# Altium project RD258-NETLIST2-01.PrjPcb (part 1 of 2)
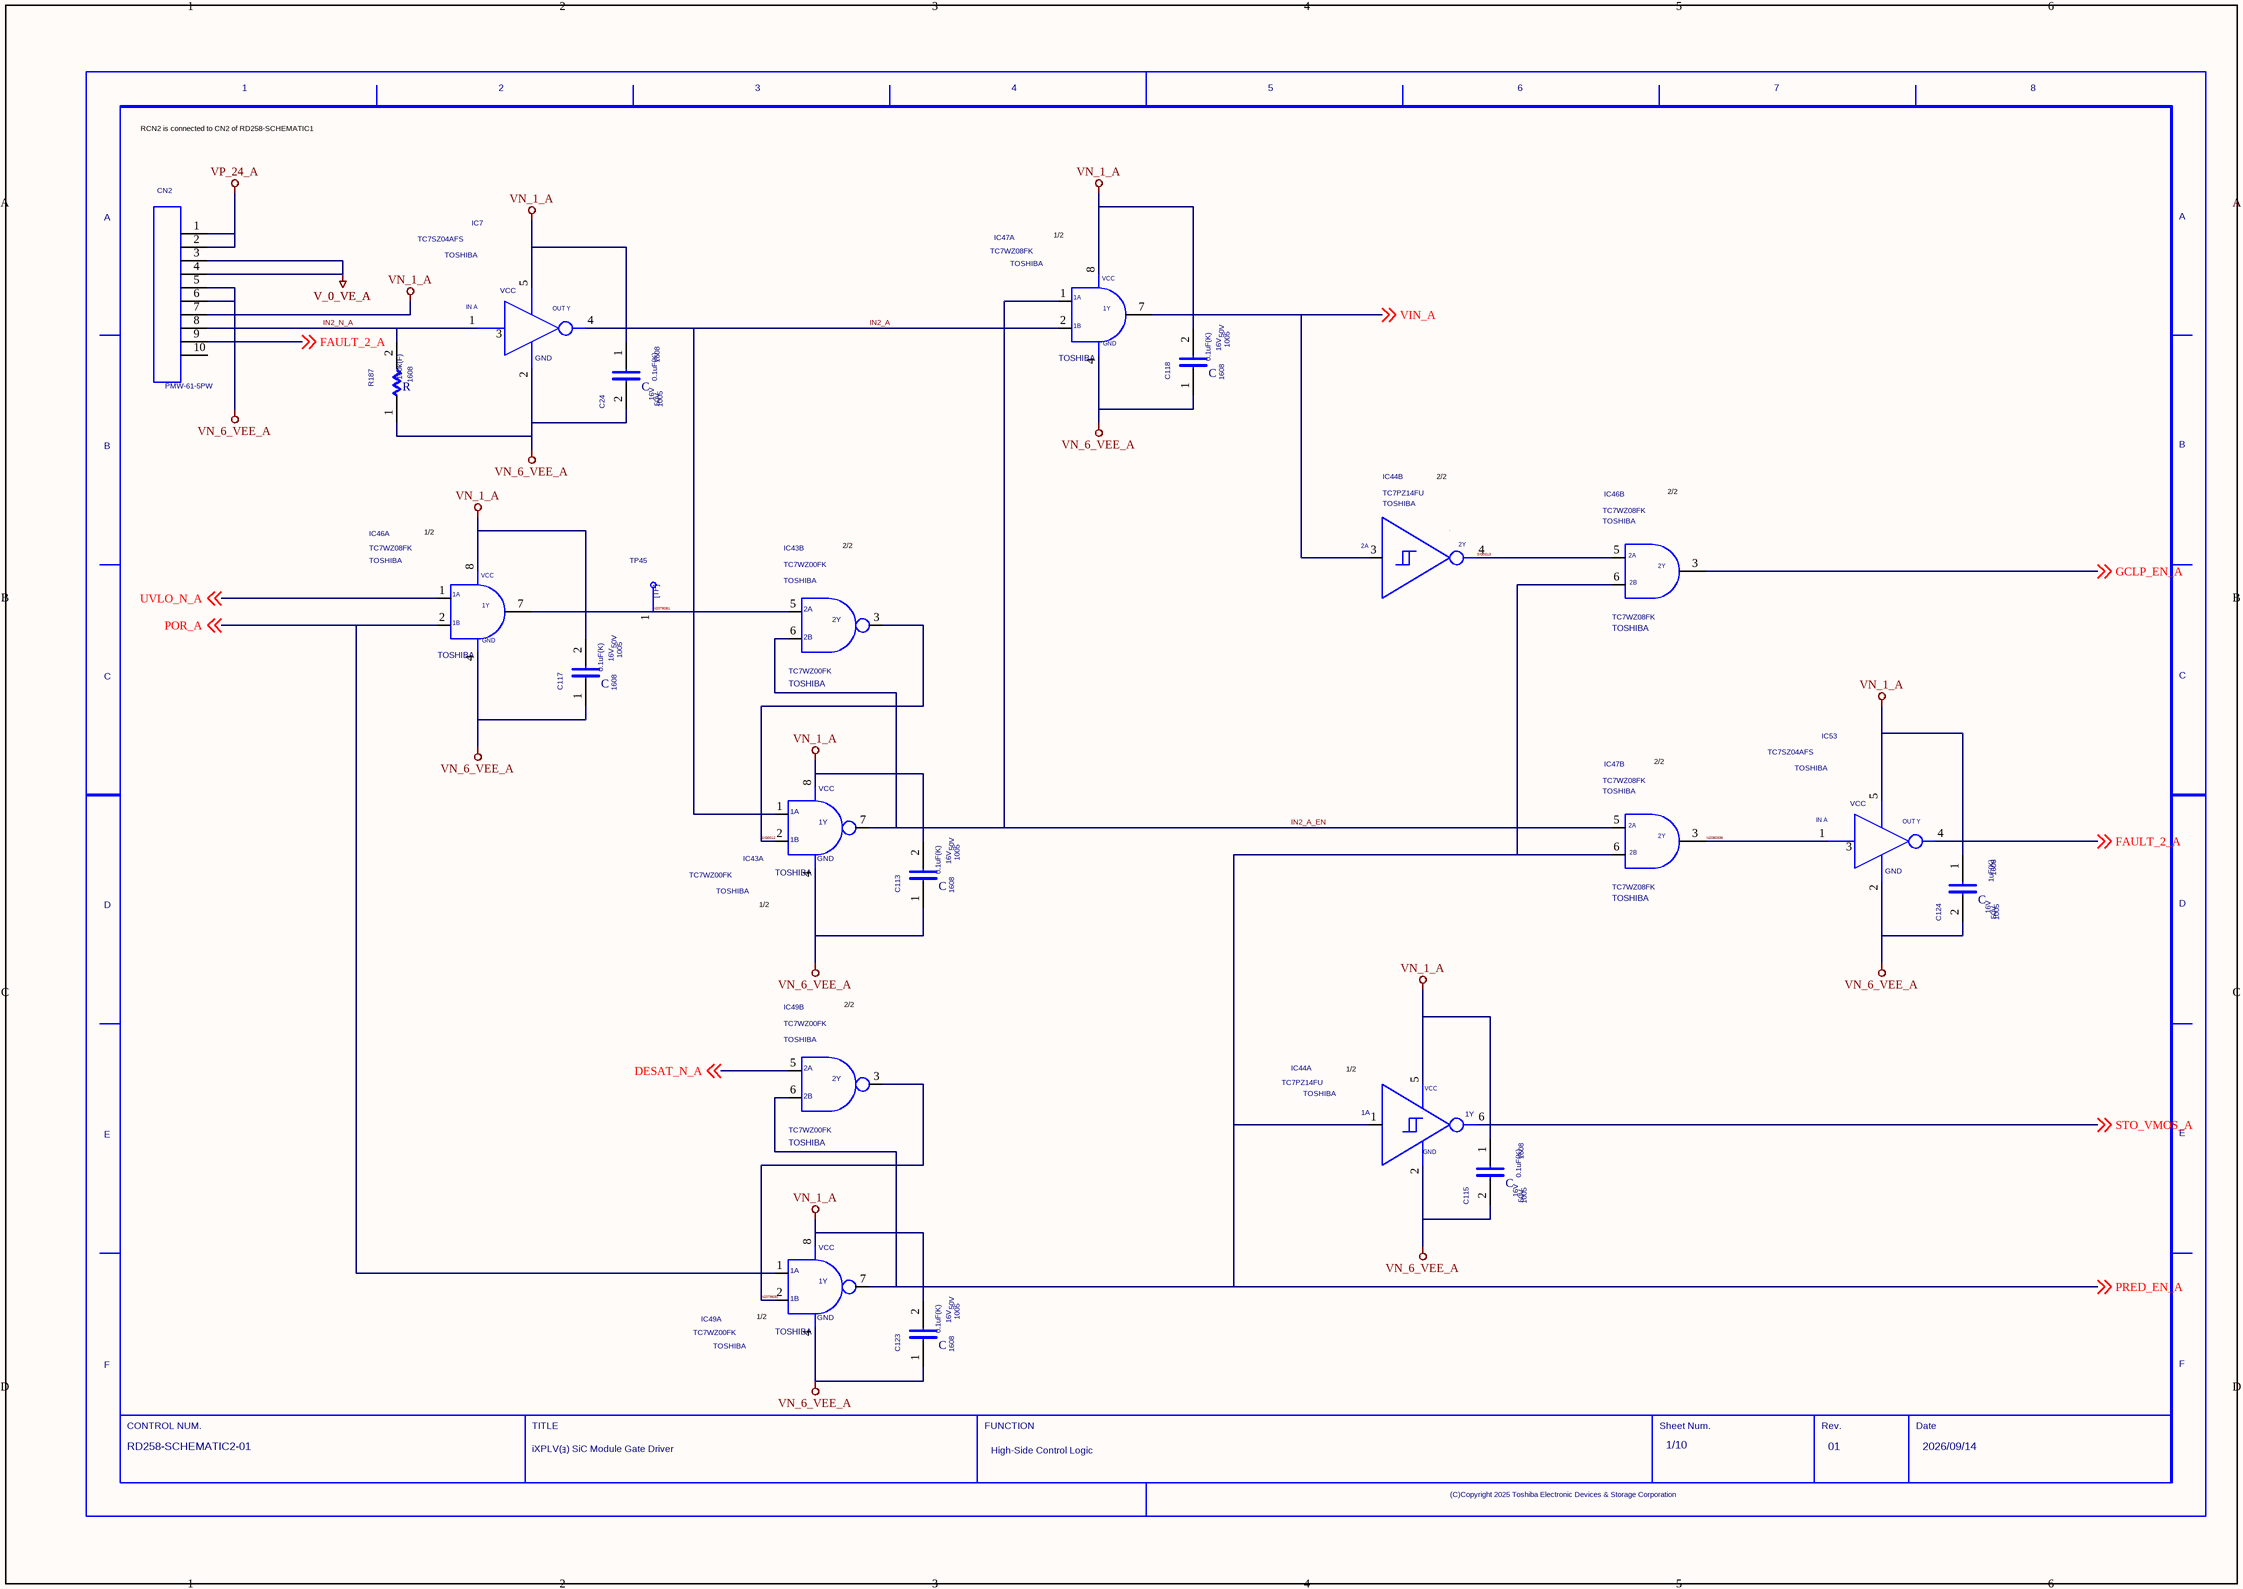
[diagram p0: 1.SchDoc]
10 sheets, 366 parts. Net scope: global (net labels, ports and power ports of the same name join across sheets).
Sheets:
  1.SchDoc
  2.SchDoc
  3.SchDoc
  4.SchDoc
  5.SchDoc
  6.SchDoc
  7.SchDoc
  8.SchDoc
  9.SchDoc
  10.SchDoc

## Sheet 1.SchDoc
size 420 x 297 mm

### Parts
(Parts that share a designator on the sheet are numbered #1, #2 ... from top to bottom, then left to right.)
C24  VAL1: 0.1uF(K)  CODE: 1005  VOLTAGE: 16V  SIZECODESMD: 1608  VAL2: 50V  (hidden comment: C)
C113  VAL1: 0.1uF(K)  CODE: 1005  VOLTAGE: 16V  SIZECODESMD: 1608  VAL2: 50V  (hidden comment: C)
C115  VAL1: 0.1uF(K)  CODE: 1005  VOLTAGE: 16V  SIZECODESMD: 1608  VAL2: 50V  (hidden comment: C)
C117  VAL1: 0.1uF(K)  CODE: 1005  VOLTAGE: 16V  SIZECODESMD: 1608  VAL2: 50V  (hidden comment: C)
C118  VAL1: 0.1uF(K)  CODE: 1005  VOLTAGE: 16V  SIZECODESMD: 1608  VAL2: 50V  (hidden comment: C)
C123  VAL1: 0.1uF(K)  CODE: 1005  VOLTAGE: 16V  SIZECODESMD: 1608  VAL2: 50V  (hidden comment: C)
C124  VAL1: 1uF(K)  CODE: 1005  VOLTAGE: 16V  SIZECODESMD: 1608  VAL2: 50V  (hidden comment: C)
CN2  VAL3: PMW-61-5PW  (hidden comment: CN9_2)
IC7  USERCOMPTEXT3: TOSHIBA  (hidden comment: TC7SZ04AFS)
IC43  VENDOR: TOSHIBA  (hidden comment: TC7WZ00FK)  (parts A,B of 2)
IC44  USERCOMPTEXT3: TOSHIBA  VAL3: TC7PZ14FU  (hidden comment: TC7PZ17FU)  (parts A,B of 2)
IC46  VENDOR: TOSHIBA  (hidden comment: TC7WZ08FK)  (parts A,B of 2)
IC47  VENDOR: TOSHIBA  (hidden comment: TC7WZ08FK)  (parts A,B of 2)
IC49  VENDOR: TOSHIBA  (hidden comment: TC7WZ00FK)  (parts A,B of 2)
IC53  USERCOMPTEXT3: TOSHIBA  (hidden comment: TC7SZ04AFS)
R187  VAL1: 100k(F)  SIZECODESMD: 1608  (hidden comment: R)
TP45  TP  (value not drawn)
U?#1  DATE: 2026/09/14  DRAWINGNUMBER: RD258-SCHEMATIC2-01  TITLE: iXPLV(ｮ) SiC Module Gate Driver  FUNCTION: High-Side Control Logic  SHEETNUMBER: 1/10  REVISION: 01  (hidden comment: WAKU_DEF100)

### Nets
V_0_VE_A: CN2.3 CN2.4
VN_1_A: C24.1 C113.2 C115.1 C117.2 C118.2 C123.2 C124.1 CN2.7 IC7.5 IC43.8 IC44.5 IC46.8 IC47.8 IC49.8 IC53.5
VN_6_VEE_A: C24.2 C113.1 C115.2 C117.1 C118.1 C123.1 C124.2 CN2.5 CN2.6 IC7.2 IC43.4 IC44.2 IC46.4 IC47.4 IC49.4 IC53.2 R187.1
VP_24_A: CN2.1 CN2.2
DESAT_N_A: IC49.5(2A) ; off-sheet DESAT_N_A
FAULT_2_A: CN2.9 IC53.4 ; off-sheet FAULT_2_A
GCLP_EN_A: IC46.3 ; off-sheet GCLP_EN_A
IN2_A: IC7.4 IC43.1 IC47.2
IN2_A_EN: IC43.6(2B) IC43.7 IC47.1 IC47.5
IN2_N_A: CN2.8 IC7.1 R187.2
N2078081: IC43.5(2A) IC46.7 TP45.1
N2078630: IC49.2 IC49.3(2Y)
N2080336: IC47.3 IC53.1
POR_A: IC46.2 IC49.1 ; off-sheet POR_A
PRED_EN_A: IC44.1 IC46.6 IC47.6 IC49.6(2B) IC49.7 ; off-sheet PRED_EN_A
SIG0012: IC43.2 IC43.3(2Y)
SIG0013: IC44.4 IC46.5
STO_VMOS_A: IC44.6 ; off-sheet STO_VMOS_A
UVLO_N_A: IC46.1 ; off-sheet UVLO_N_A
VIN_A: IC44.3 IC47.7 ; off-sheet VIN_A

Not connected (* = marked no-connect by the designer): CN2 10; IC7 3; IC53 3

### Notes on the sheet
- RCN2 is connected to CN2 of RD258-SCHEMATIC1
- (near IC47) 1/2
- (near IC46) 1/2
- 2/2
- (near IC43) 1/2
- (near IC44) 1/2
- (near IC49) 1/2

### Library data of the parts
C24 C113 C115 C117 C118 C123 C124 = C: TIME: 08:48:12; UPDATEUSER: HP_Z8_KEYSHOT; SAVECOUNT: 2; TC1: 0; PSPICETEMPLATE: C^@REFDES %1 %2 ?TOLERANCE¦C^@REFDES¦ @VALUE ?IC/IC=@IC/ TC=@TC1,@TC2 ?TOLERANCE¦\n.model C^@REFDES CAP C=1 DEV=@TOLERANCE% TC1=@TC1 TC2=@TC2 VC1=@VC1 VC2=@VC2¦; ORIGINALSYMBOLORIGIN: (0,0); INSTANCENAME: INS2265204
CN2 = CN10_1: TIME: 08:48:13; UPDATEUSER: t5459927; UPDATETIME: 15:38:59; SAVECOUNT: 3; PSPICETEMPLATE: X^@REFDES %1 %2 %3 %4 %5 %6 %7 %8 %9 %10 %M1 %M2 @MODEL; USER_VALUE: XG4A-1031; OriginalSymbolOrigin: (0,0)
IC7 IC53 = TC7SZ04AFS: TIME: 11:55:02; UPDATEUSER: t5459927; UPDATETIME: 19:30:29; SAVECOUNT: 6; PSPICETEMPLATE: X^@REFDES %INA %GND %NC %OUTY %VCC @MODEL; OriginalSymbolOrigin: (0,-5080); INSTANCENAME: INS2254048
IC43 IC49 = TC7WZ00FK_1: TIME: 08:52:39; UPDATEUSER: sptcae09; UPDATETIME: 16:09:46; SAVECOUNT: 9; SWAP_INFO: (S1+S2); ORDER: $pOrder; SPLIT_INST: TRUE; ・: 20mA; USER_VALUE: TC7W00FK; PSPICETEMPLATE: X^@REFDES %1A %1B %2Y %GND %2A %2B %1Y %VCC @MODEL; DESCRIPTION-A: NAND 2ch Logic; ORIGINALSYMBOLORIGIN: (2540,-2540); CaptureCellPackProp: TC7WZ00FK_1A; INSTANCENAME: INS2253652
IC44 = TC7PZ14FU_2: TIME: 11:55:01; UPDATEUSER: t5459927; UPDATETIME: 19:09:34; SAVECOUNT: 7; SPLIT_INST: TRUE; PSPICETEMPLATE: X^@REFDES %1A %GND %2A %2Y %VCC %1Y @MODEL; SWAP_INFO: (S1+S2); OriginalSymbolOrigin: (5080,15240); CaptureCellPackProp: TC7PZ14FU_2A; FUNCN: TC7PZ14FU_1; INSTANCENAME: INS2254016
IC46 IC47 = TC7WZ08FK_1: TIME: 08:52:39; UPDATEUSER: sptcae09; UPDATETIME: 16:09:46; SAVECOUNT: 5; SWAP_INFO: (S1+S2); ORDER: $pOrder; SPLIT_INST: TRUE; ・: 20mA; USER_VALUE: TC7W00FK; PSPICETEMPLATE: X^@REFDES %1A %1B %2Y %GND %2A %2B %1Y %VCC @MODEL; DESCRIPTION-A: NAND 2ch Logic; ORIGINALSYMBOLORIGIN: (2540,-2540); CaptureCellPackProp: TC7WZ08FK_1A; INSTANCENAME: INS2254084
R187 = R: TIME: 08:48:13; UPDATEUSER: HP_Z8_KEYSHOT; SAVECOUNT: 2; VAL2: 100mW; TC1: 0; PSPICETEMPLATE: R^@REFDES %1 %2 ?TOLERANCE¦R^@REFDES¦ @VALUE TC=@TC1,@TC2 ?TOLERANCE¦\n.model R^@REFDES RES R=1 DEV=@TOLERANCE% TC1=@TC1 TC2=@TC2¦; ORIGINALSYMBOLORIGIN: (0,0); INSTANCENAME: INS2263832
TP45 = TP: TIME: 16:12:21; UPDATEUSER: fukuda-y; UPDATETIME: 16:18:11; SAVECOUNT: 2; SAVEAREA0: -242,-92,12810,7836; ORIGINALSYMBOLORIGIN: (0,0); INSTANCENAME: INS2253720
U?#1 = WAKU_DEF100: PLOTTIME: HH:MM; SAVEAREA0: -63393,-16950,474261,314592; TIME: 14:30:25; UPDATEUSER: t5459927; UPDATETIME: 14:14:23; SAVECOUNT: 4; OriginalSymbolOrigin: (10160,284480); SHTSAVECOUNT: 37

## Sheet 2.SchDoc
size 420 x 297 mm
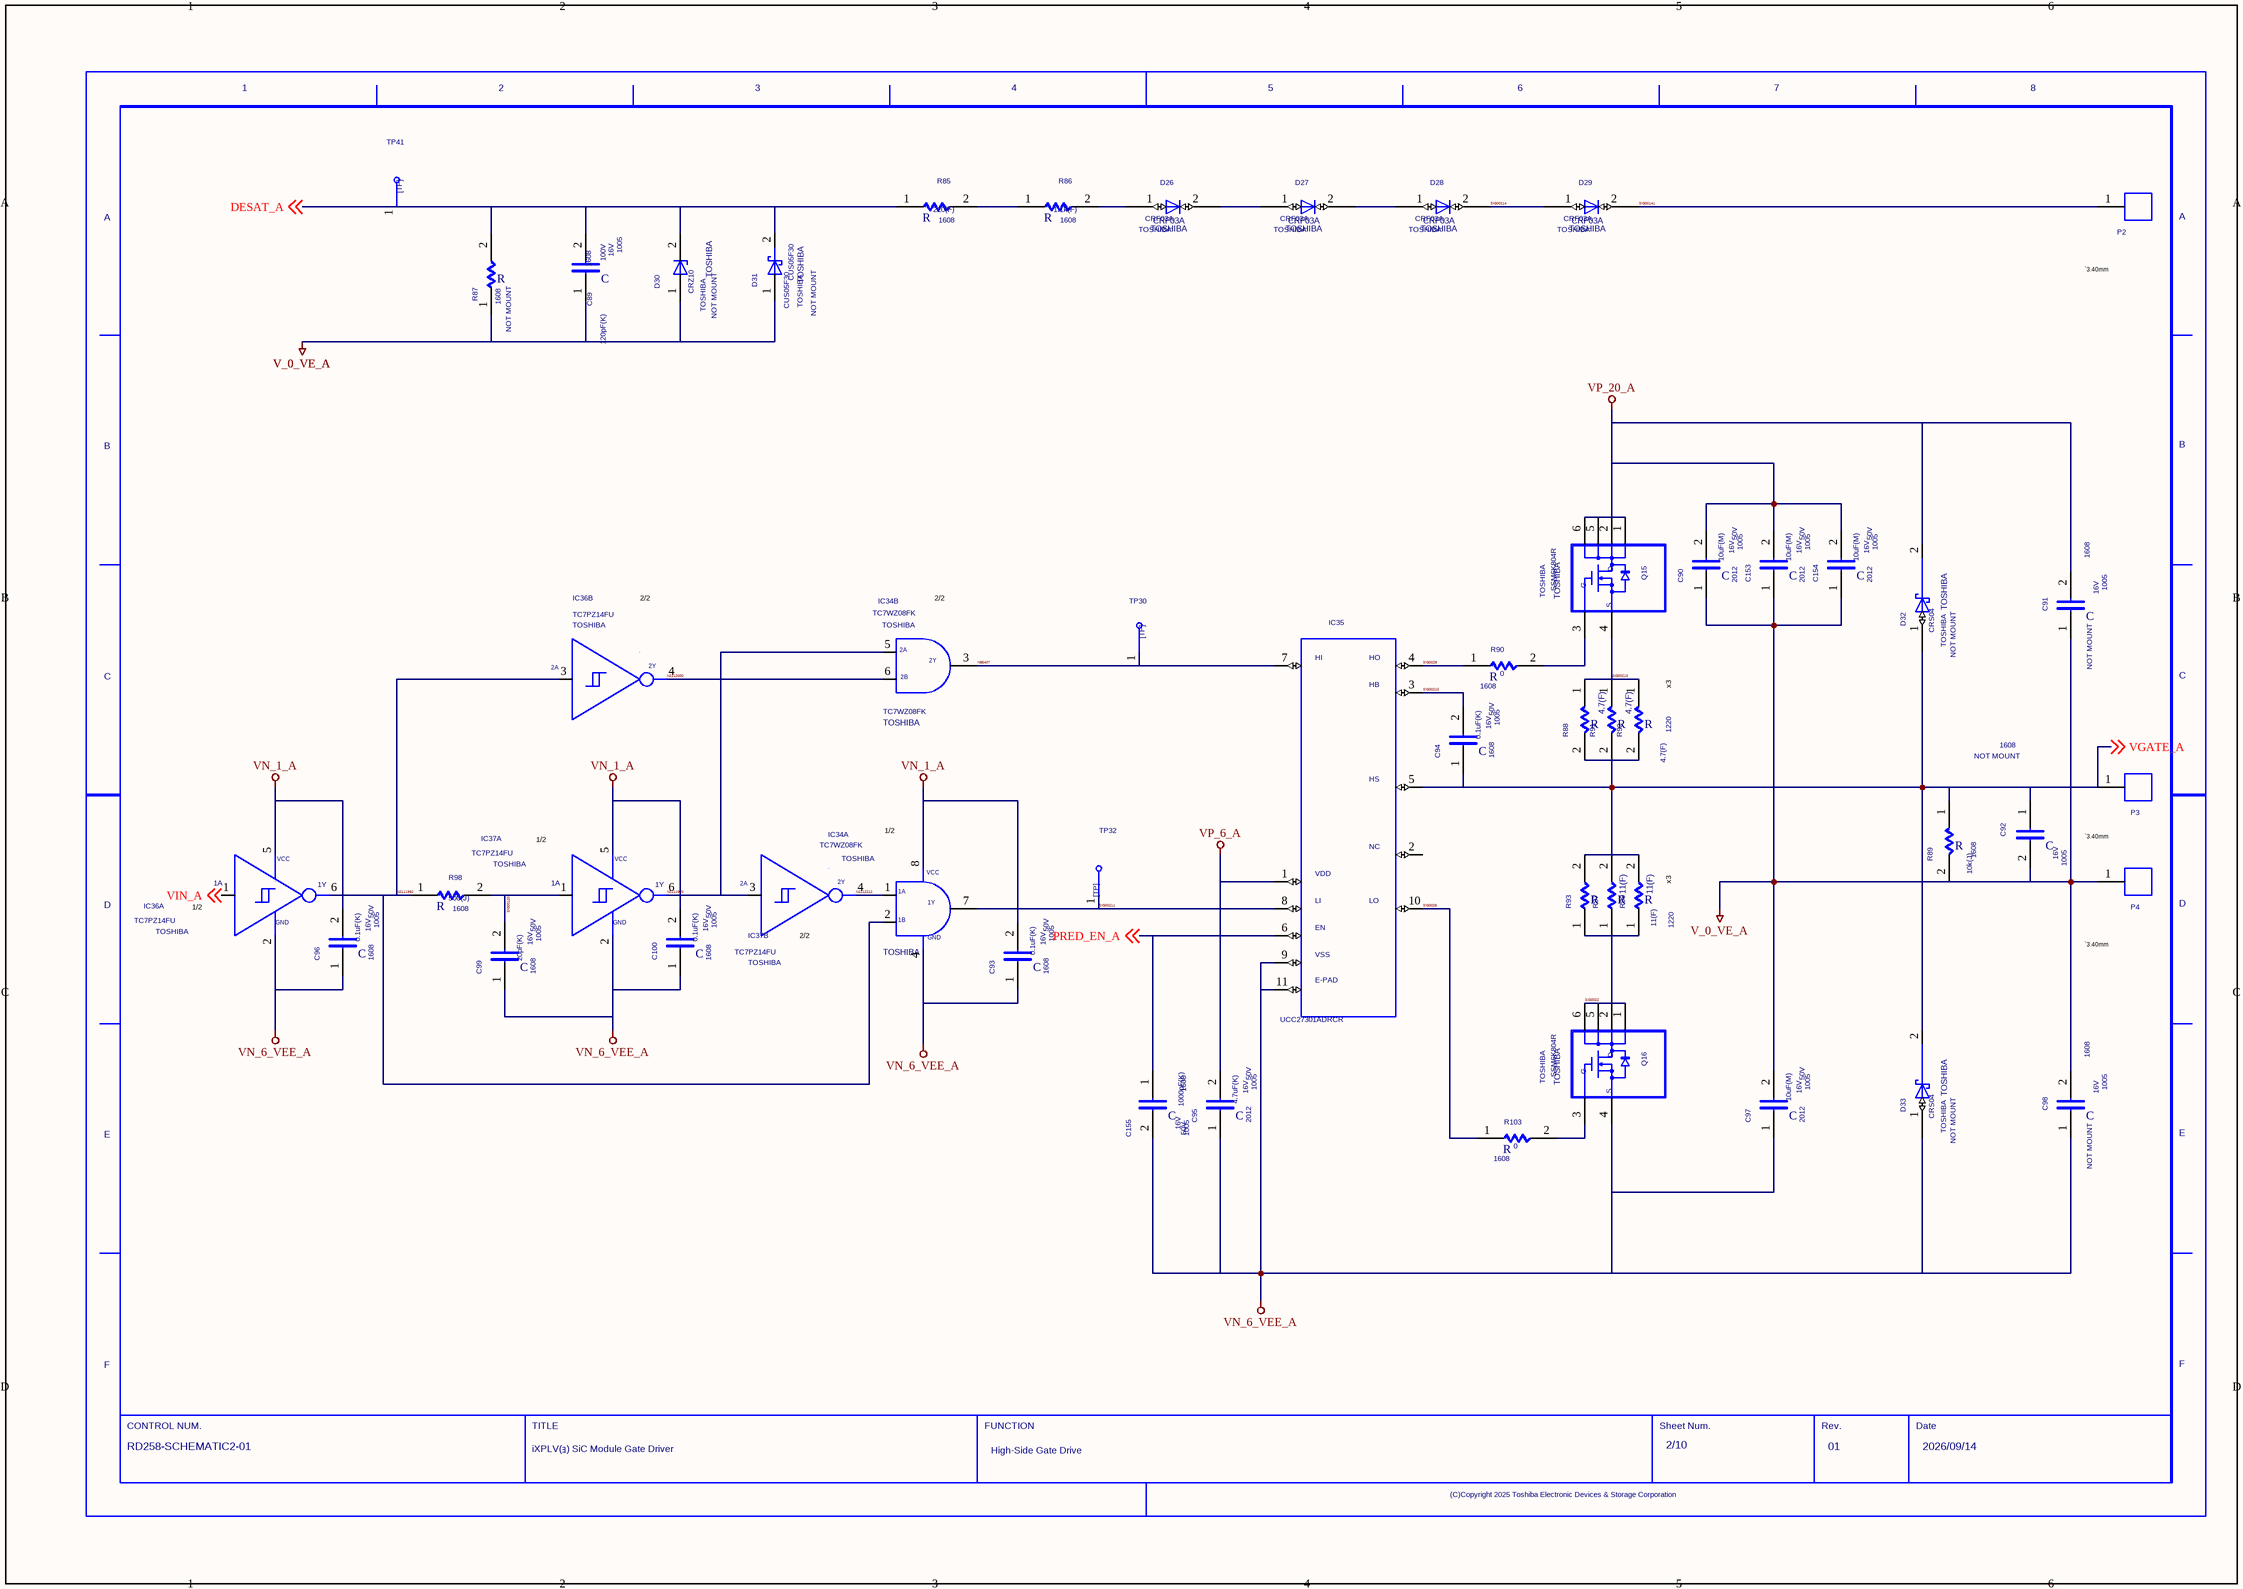
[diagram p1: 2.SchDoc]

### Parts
(Parts that share a designator on the sheet are numbered #1, #2 ... from top to bottom, then left to right.)
C89  VAL1: 120pF(K)  CODE: 1005  VOLTAGE: 16V  SIZECODESMD: 1608  VAL2: 100V  (hidden comment: C)
C90  VAL1: 10uF(M)  CODE: 1005  VOLTAGE: 16V  SIZECODESMD: 2012  VAL2: 50V  (hidden comment: C)
C91  CODE: 1005  VOLTAGE: 16V  NOTMOUNT: NOT MOUNT  SIZECODESMD: 1608  (hidden comment: C)
C92  CODE: 1005  VOLTAGE: 16V  NOTMOUNT: NOT MOUNT  SIZECODESMD: 1608  (hidden comment: C)
C93  VAL1: 0.1uF(K)  CODE: 1005  VOLTAGE: 16V  SIZECODESMD: 1608  VAL2: 50V  (hidden comment: C)
C94  VAL1: 0.1uF(K)  CODE: 1005  VOLTAGE: 16V  SIZECODESMD: 1608  VAL2: 50V  (hidden comment: C)
C95  VAL1: 4.7uF(K)  CODE: 1005  VOLTAGE: 16V  SIZECODESMD: 2012  VAL2: 50V  (hidden comment: C)
C96  VAL1: 0.1uF(K)  CODE: 1005  VOLTAGE: 16V  SIZECODESMD: 1608  VAL2: 50V  (hidden comment: C)
C97  VAL1: 10uF(M)  CODE: 1005  VOLTAGE: 16V  SIZECODESMD: 2012  VAL2: 50V  (hidden comment: C)
C98  CODE: 1005  VOLTAGE: 16V  NOTMOUNT: NOT MOUNT  SIZECODESMD: 1608  (hidden comment: C)
C99  VAL1: 20pF(K)  CODE: 1005  VOLTAGE: 16V  SIZECODESMD: 1608  VAL2: 50V  (hidden comment: C)
C100  VAL1: 0.1uF(K)  CODE: 1005  VOLTAGE: 16V  SIZECODESMD: 1608  VAL2: 50V  (hidden comment: C)
C153  VAL1: 10uF(M)  CODE: 1005  VOLTAGE: 16V  SIZECODESMD: 2012  VAL2: 50V  (hidden comment: C)
C154  VAL1: 10uF(M)  CODE: 1005  VOLTAGE: 16V  SIZECODESMD: 2012  VAL2: 50V  (hidden comment: C)
C155  VAL1: 1000pF(K)  CODE: 1005  VOLTAGE: 16V  SIZECODESMD: 1608  VAL2: 50V  (hidden comment: C)
D26  VENDOR: TOSHIBA  (hidden comment: CRF03A)
D27  VENDOR: TOSHIBA  (hidden comment: CRF03A)
D28  VENDOR: TOSHIBA  (hidden comment: CRF03A)
D29  VENDOR: TOSHIBA  (hidden comment: CRF03A)
D30  VENDOR: TOSHIBA  NOTMOUNT: NOT MOUNT  (hidden comment: CRZ10)
D31  VENDOR: TOSHIBA  NOTMOUNT: NOT MOUNT  (hidden comment: CUS05F30)
D32  VENDOR: TOSHIBA  NOTMOUNT: NOT MOUNT  (hidden comment: CRS04)
D33  VENDOR: TOSHIBA  NOTMOUNT: NOT MOUNT  (hidden comment: CRS04)
IC34  VENDOR: TOSHIBA  (hidden comment: TC7WZ08FK)  (parts A,B of 2)
IC35  VAL3: UCC27301ADRCR  (hidden comment: UCC27301A)
IC36  USERCOMPTEXT3: TOSHIBA  VAL3: TC7PZ14FU  (hidden comment: TC7PZ17FU)  (parts A,B of 2)
IC37  USERCOMPTEXT3: TOSHIBA  VAL3: TC7PZ14FU  (hidden comment: TC7PZ17FU)  (parts A,B of 2)
P2  TH  (value not drawn)
P3  TH  (value not drawn)
P4  TH  (value not drawn)
Q15  VENDOR: TOSHIBA  (hidden comment: SSM6K804R)
Q16  VENDOR: TOSHIBA  (hidden comment: SSM6K804R)
R85  VAL1: 220(F)  SIZECODESMD: 1608  (hidden comment: R)
R86  VAL1: 1.1k(F)  SIZECODESMD: 1608  (hidden comment: R)
R87  NOTMOUNT: NOT MOUNT  SIZECODESMD: 1608  (hidden comment: R)
R88  VAL1: 4.7(F)  SIZECODESMD: 1220  (hidden comment: R)
R89  VAL1: 10k(J)  SIZECODESMD: 1608  (hidden comment: R)
R90  VAL1: 0  SIZECODESMD: 1608  (hidden comment: R)
R91  VAL1: 4.7(F)  (hidden comment: R)
R92  VAL1: 4.7(F)  (hidden comment: R)
R93  VAL1: 11(F)  SIZECODESMD: 1220  (hidden comment: R)
R97  VAL1: 11(F)  (hidden comment: R)
R98  VAL1: 500(J)  SIZECODESMD: 1608  (hidden comment: R)
R99  VAL1: 11(F)  (hidden comment: R)
R103  VAL1: 0  SIZECODESMD: 1608  (hidden comment: R)
TP30  TP  (value not drawn)
TP32  TP  (value not drawn)
TP41  TP  (value not drawn)
U?#2  DATE: 2026/09/14  DRAWINGNUMBER: RD258-SCHEMATIC2-01  TITLE: iXPLV(ｮ) SiC Module Gate Driver  FUNCTION: High-Side Gate Drive  SHEETNUMBER: 2/10  REVISION: 01  (hidden comment: WAKU_DEF100)

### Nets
V_0_VE_A: C89.1 C90.1 C91.1 C92.2 C97.2 C98.2 C153.1 C154.1 D30.1(A) D31.1(A) P4.1 R87.1 R89.2
VN_1_A: C93.2 C96.2 C100.2 IC34.8 IC36.5 IC37.5
VN_6_VEE_A: C93.1 C95.1 C96.1 C97.1 C98.1 C99.1 C100.1 C155.2 D33.1(A) IC34.4 IC35.9 IC35.11 IC36.2 IC37.2 Q16.4
VP_6_A: C95.2 IC35.1
VP_20_A: C90.2 C91.2 C153.2 C154.2 D32.2(C) Q15.1 Q15.2 Q15.5 Q15.6
DESAT_A: C89.2 D30.2(C) D31.2(C) R85.1 R87.2 TP41.1 ; off-sheet DESAT_A
N85407: IC34.3 IC35.7 TP30.1
N2111970: IC34.5 IC37.3 IC37.6
N2111992: IC34.2 IC36.3 IC36.6 R98.1
N2112000: IC34.6 IC36.4
N2112212: IC34.1 IC37.4
PRED_EN_A: C155.1 IC35.6 ; off-sheet PRED_EN_A
SIG0022: Q16.1 Q16.2 Q16.5 Q16.6 R93.1 R97.1 R99.1
SIG0026: IC35.10 R103.1
SIG0028: IC35.4 R90.1
SIG00120: C99.2 IC37.1 R98.2
SIG00130: Q16.3 R103.2
SIG00136: Q15.3 R90.2
SIG00137: R85.2 R86.1
SIG00138: D26.1(A) R86.2
SIG00139: D26.2(C) D27.1(A)
SIG00140: D27.2(C) D28.1(A)
SIG00141: D29.2(C) P2.1
SIG00210: C94.2 IC35.3
SIG00211: IC34.7 IC35.8 TP32.1
SIG00213: Q15.4 R88.1 R91.1 R92.1
SIG00214: D28.2(C) D29.1(A)
VGATE_A: C92.1 C94.1 D32.1(A) D33.2(C) IC35.5 P3.1 R88.2 R89.1 R91.2 R92.2 R93.2 R97.2 R99.2 ; off-sheet VGATE_A
VIN_A: IC36.1 ; off-sheet VIN_A

Not connected (* = marked no-connect by the designer): IC35 2

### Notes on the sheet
- `3.40mm
  TH
- 2/2
- (near IC34) 2/2
- (near R92) x3
- (near IC37) 1/2
- (near IC34) 1/2
- (near IC36) 1/2
- (near IC37) 2/2
- (near R99) x3

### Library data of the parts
C89 C90 C93-C97 C99 C100 C153-C155 = C: as C24 on sheet 1
C91 C92 C98 = C: TIME: 08:48:12; UPDATEUSER: HP_Z8_KEYSHOT; SAVECOUNT: 2; TC1: 0; PSPICETEMPLATE: C^@REFDES %1 %2 ?TOLERANCE¦C^@REFDES¦ @VALUE ?IC/IC=@IC/ TC=@TC1,@TC2 ?TOLERANCE¦\n.model C^@REFDES CAP C=1 DEV=@TOLERANCE% TC1=@TC1 TC2=@TC2 VC1=@VC1 VC2=@VC2¦; ORIGINALSYMBOLORIGIN: (0,0); INSTANCENAME: INS2266227
D26-D29 = CRF03A: TIME: 08:48:14; UPDATEUSER: HP_Z8_KEYSHOT; SAVECOUNT: 2; PSPICETEMPLATE: X^@REFDES %A %C @MODEL; OriginalSymbolOrigin: (0,0); INSTANCENAME: INS2254974
D30 = CRZ10: TIME: 14:49:55; UPDATEUSER: fukuda-y; UPDATETIME: 08:18:42; SAVECOUNT: 6; SAVEAREA0: -4630,-153,17114,13055; PSPICETEMPLATE: X^@REFDES %A %C @MODEL; ORIGINALSYMBOLORIGIN: (0,0); INSTANCENAME: INS2255026
D31 = CUS05F30: TIME: 14:49:55; UPDATEUSER: fukuda-y; UPDATETIME: 08:16:22; SAVECOUNT: 9; SAVEAREA0: -4630,-153,17114,13055; PSPICETEMPLATE: X^@REFDES %A %C @MODEL; ORIGINALSYMBOLORIGIN: (0,0); INSTANCENAME: INS2255944
D32 D33 = CRS04: TIME: 08:48:14; UPDATEUSER: HP_Z8_KEYSHOT; SAVECOUNT: 2; PSPICETEMPLATE: X^@REFDES %A %C @MODEL; OriginalSymbolOrigin: (0,0); INSTANCENAME: INS2256112
IC34 = TC7WZ08FK_1: TIME: 08:52:39; UPDATEUSER: sptcae09; UPDATETIME: 16:09:46; SAVECOUNT: 9; SWAP_INFO: (S1+S2); ORDER: $pOrder; SPLIT_INST: TRUE; ・: 20mA; USER_VALUE: TC7W00FK; PSPICETEMPLATE: X^@REFDES %1A %1B %2Y %GND %2A %2B %1Y %VCC @MODEL; DESCRIPTION-A: NAND 2ch Logic; ORIGINALSYMBOLORIGIN: (2540,-2540); CaptureCellPackProp: TC7WZ08FK_1A; INSTANCENAME: INS2255192
IC35 = UCC27301A: TIME: 08:48:14; UPDATEUSER: t5459927; UPDATETIME: 20:55:41; SAVECOUNT: 11; PSPICETEMPLATE: X^@REFDES %VDD %NC %HB %HO %HS %EN %HI %LI %VSS %LO %THERMAL_PAD @MODEL; OriginalSymbolOrigin: (5080,60960)
IC36 IC37 = TC7PZ14FU_2: as IC44 on sheet 1
P2 = TH: TIME: 18:11:32; UPDATEUSER: w20165dm; SAVECOUNT: 1; PSPICETEMPLATE: X^@REFDES %1 @MODEL; ORIGINALSYMBOLORIGIN: (0,0); INSTANCENAME: INS2255754
P3 = TH: TIME: 18:11:32; UPDATEUSER: w20165dm; SAVECOUNT: 1; PSPICETEMPLATE: X^@REFDES %1 @MODEL; ORIGINALSYMBOLORIGIN: (0,0); INSTANCENAME: INS2255180
P4 = TH: TIME: 18:11:32; UPDATEUSER: w20165dm; SAVECOUNT: 1; PSPICETEMPLATE: X^@REFDES %1 @MODEL; ORIGINALSYMBOLORIGIN: (0,0); INSTANCENAME: INS2256066
Q15 Q16 = SSM6K804R: TIME: 08:48:15; UPDATEUSER: HP_Z8_KEYSHOT; SAVECOUNT: 14; SAVEAREA0: -7120,-295,29516,23636; ORIGINALSYMBOLORIGIN: (0,0); PSPICETEMPLATE: X^@REFDES %1 %2 %3 %4 %5 %6 @MODEL; INSTANCENAME: INS2255292
R85 R86 R98 = R: as R187 on sheet 1
R87 = R: TIME: 08:48:13; UPDATEUSER: HP_Z8_KEYSHOT; SAVECOUNT: 2; VAL2: 0.125; TC1: 0; PSPICETEMPLATE: R^@REFDES %1 %2 ?TOLERANCE¦R^@REFDES¦ @VALUE TC=@TC1,@TC2 ?TOLERANCE¦\n.model R^@REFDES RES R=1 DEV=@TOLERANCE% TC1=@TC1 TC2=@TC2¦; ORIGINALSYMBOLORIGIN: (0,0); INSTANCENAME: INS2263832
R88 R93 = R: TIME: 08:48:13; UPDATEUSER: HP_Z8_KEYSHOT; SAVECOUNT: 2; VAL2: 1W; TC1: 0; PSPICETEMPLATE: R^@REFDES %1 %2 ?TOLERANCE¦R^@REFDES¦ @VALUE TC=@TC1,@TC2 ?TOLERANCE¦\n.model R^@REFDES RES R=1 DEV=@TOLERANCE% TC1=@TC1 TC2=@TC2¦; ORIGINALSYMBOLORIGIN: (0,0); INSTANCENAME: INS2256002
R89 = R: TIME: 08:48:13; UPDATEUSER: HP_Z8_KEYSHOT; SAVECOUNT: 2; VAL2: 100mW; TC1: 0; PSPICETEMPLATE: R^@REFDES %1 %2 ?TOLERANCE¦R^@REFDES¦ @VALUE TC=@TC1,@TC2 ?TOLERANCE¦\n.model R^@REFDES RES R=1 DEV=@TOLERANCE% TC1=@TC1 TC2=@TC2¦; ORIGINALSYMBOLORIGIN: (0,0); INSTANCENAME: INS2266059
R90 R103 = R: TIME: 08:48:13; UPDATEUSER: HP_Z8_KEYSHOT; SAVECOUNT: 2; VAL2: 0.125; PSPICETEMPLATE: R^@REFDES %1 %2 ?TOLERANCE¦R^@REFDES¦ @VALUE TC=@TC1,@TC2 ?TOLERANCE¦\n.model R^@REFDES RES R=1 DEV=@TOLERANCE% TC1=@TC1 TC2=@TC2¦; ORIGINALSYMBOLORIGIN: (0,0); INSTANCENAME: INS2256002
R91 R92 R97 R99 = R: TIME: 08:48:13; UPDATEUSER: HP_Z8_KEYSHOT; SAVECOUNT: 2; VAL2: 1W; TC1: 0; PSPICETEMPLATE: R^@REFDES %1 %2 ?TOLERANCE¦R^@REFDES¦ @VALUE TC=@TC1,@TC2 ?TOLERANCE¦\n.model R^@REFDES RES R=1 DEV=@TOLERANCE% TC1=@TC1 TC2=@TC2¦; ORIGINALSYMBOLORIGIN: (0,0); SIZECODESMD: 1220; INSTANCENAME: INS2256002
TP30 = TP: TIME: 16:12:21; UPDATEUSER: fukuda-y; UPDATETIME: 16:18:11; SAVECOUNT: 2; SAVEAREA0: -242,-92,12810,7836; ORIGINALSYMBOLORIGIN: (0,0); INSTANCENAME: INS2255892
TP32 = TP: TIME: 16:12:21; UPDATEUSER: fukuda-y; UPDATETIME: 16:18:11; SAVECOUNT: 2; SAVEAREA0: -242,-92,12810,7836; ORIGINALSYMBOLORIGIN: (0,0); INSTANCENAME: INS2255530
TP41 = TP: TIME: 16:12:21; UPDATEUSER: fukuda-y; UPDATETIME: 16:18:11; SAVECOUNT: 2; SAVEAREA0: -242,-92,12810,7836; ORIGINALSYMBOLORIGIN: (0,0); INSTANCENAME: INS2255794
U?#2 = WAKU_DEF100: PLOTTIME: HH:MM; SAVEAREA0: -63393,-16950,474261,314592; TIME: 14:30:25; UPDATEUSER: t5459927; UPDATETIME: 14:20:04; SAVECOUNT: 4; OriginalSymbolOrigin: (10160,284480); SHTSAVECOUNT: 41

## Sheet 3.SchDoc
size 420 x 297 mm
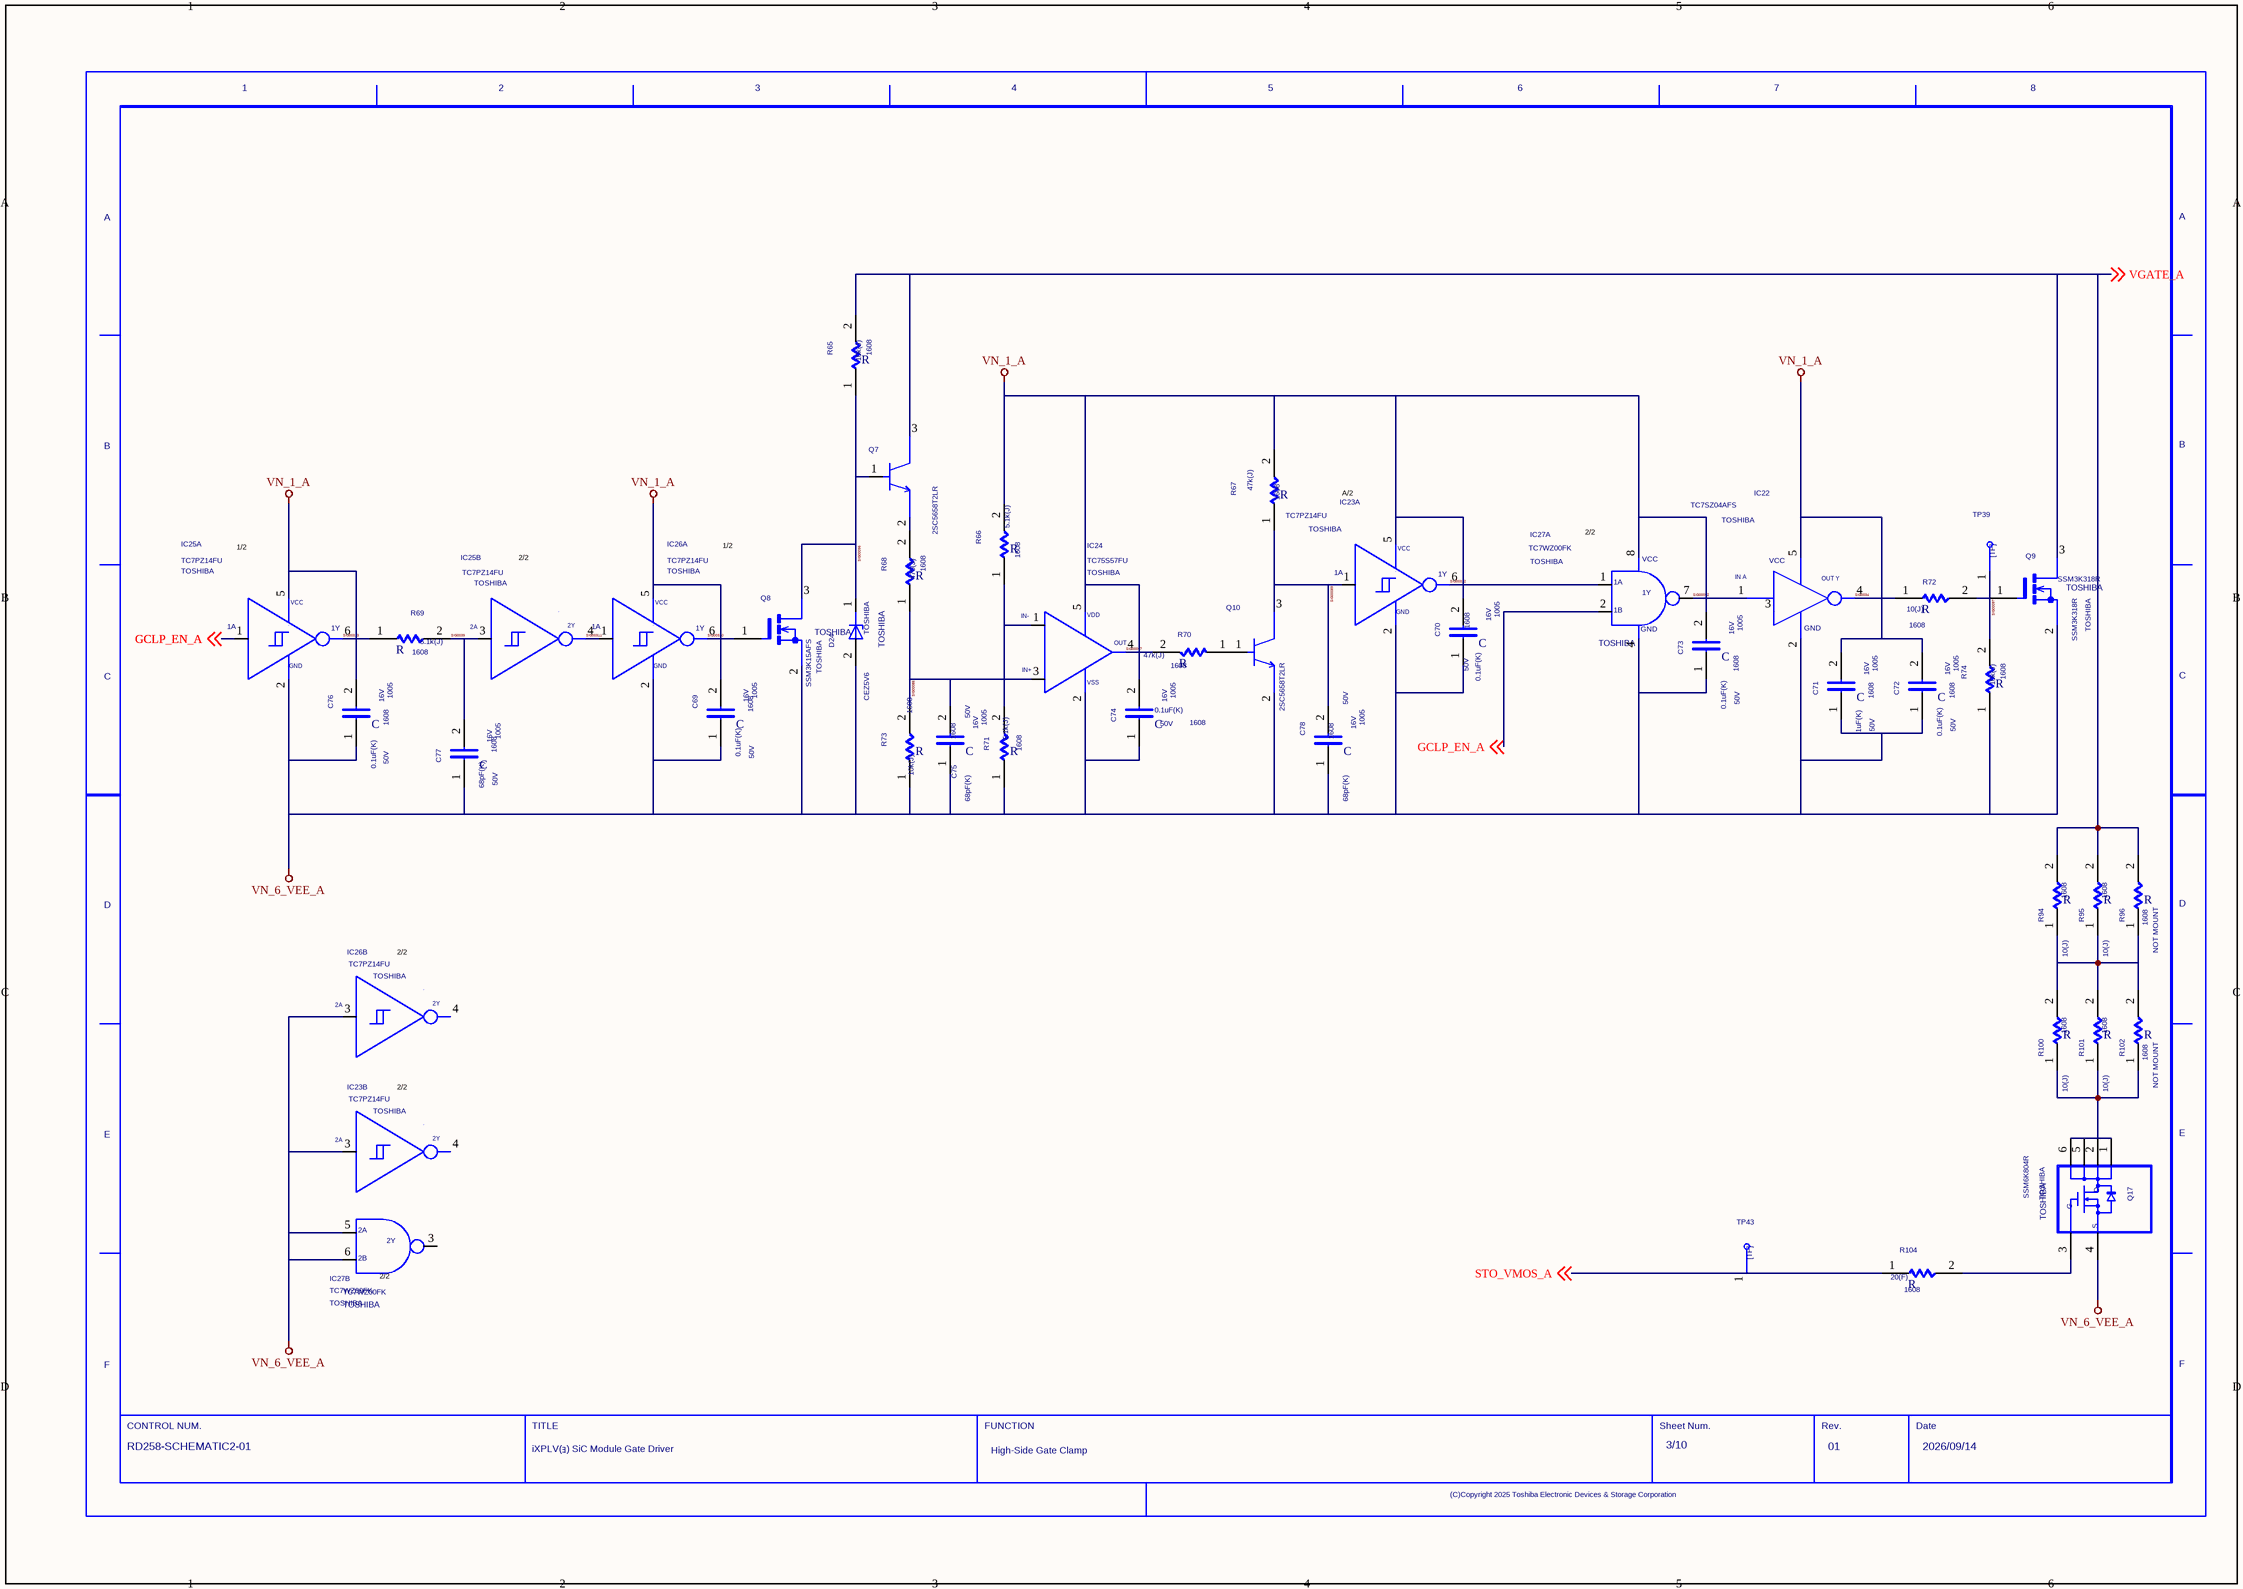
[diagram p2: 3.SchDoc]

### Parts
(Parts that share a designator on the sheet are numbered #1, #2 ... from top to bottom, then left to right.)
C69  VAL1: 0.1uF(K)  CODE: 1005  VOLTAGE: 16V  SIZECODESMD: 1608  VAL2: 50V  (hidden comment: C)
C70  VAL1: 0.1uF(K)  CODE: 1005  VOLTAGE: 16V  SIZECODESMD: 1608  VAL2: 50V  (hidden comment: C)
C71  VAL1: 1uF(K)  CODE: 1005  VOLTAGE: 16V  SIZECODESMD: 1608  VAL2: 50V  (hidden comment: C)
C72  VAL1: 0.1uF(K)  CODE: 1005  VOLTAGE: 16V  SIZECODESMD: 1608  VAL2: 50V  (hidden comment: C)
C73  VAL1: 0.1uF(K)  CODE: 1005  VOLTAGE: 16V  SIZECODESMD: 1608  VAL2: 50V  (hidden comment: C)
C74  VAL1: 0.1uF(K)  CODE: 1005  VOLTAGE: 16V  SIZECODESMD: 1608  VAL2: 50V  (hidden comment: C)
C75  VAL1: 68pF(K)  CODE: 1005  VOLTAGE: 16V  SIZECODESMD: 1608  VAL2: 50V  (hidden comment: C)
C76  VAL1: 0.1uF(K)  CODE: 1005  VOLTAGE: 16V  SIZECODESMD: 1608  VAL2: 50V  (hidden comment: C)
C77  VAL1: 68pF(K)  CODE: 1005  VOLTAGE: 16V  SIZECODESMD: 1608  VAL2: 50V  (hidden comment: C)
C78  VAL1: 68pF(K)  CODE: 1005  VOLTAGE: 16V  SIZECODESMD: 1608  VAL2: 50V  (hidden comment: C)
D24  VENDOR: TOSHIBA  (hidden comment: CEZ5V6)
IC22  USERCOMPTEXT3: TOSHIBA  (hidden comment: TC7SZ04AFS)
IC23  USERCOMPTEXT3: TOSHIBA  VAL3: TC7PZ14FU  (hidden comment: TC7PZ17FU)  (parts A,B of 2)
IC24  USERCOMPTEXT3: TOSHIBA  (hidden comment: TC75S57FU)
IC25  USERCOMPTEXT3: TOSHIBA  VAL3: TC7PZ14FU  (hidden comment: TC7PZ17FU)  (parts A,B of 2)
IC26  USERCOMPTEXT3: TOSHIBA  VAL3: TC7PZ14FU  (hidden comment: TC7PZ17FU)  (parts A,B of 2)
IC27  VENDOR: TOSHIBA  (hidden comment: TC7WZ00FK)  (parts A,B of 2)
Q7  VAL3: 2SC5658T2LR  (hidden comment: 2SC5658J)
Q8  VENDOR: TOSHIBA  (hidden comment: SSM3K15AFS)
Q9  VENDOR: TOSHIBA  (hidden comment: SSM3K318R)
Q10  VAL3: 2SC5658T2LR  (hidden comment: 2SC5658J)
Q17  VENDOR: TOSHIBA  (hidden comment: SSM6K804R)
R65  VAL1: 10k(J)  SIZECODESMD: 1608  (hidden comment: R)
R66  VAL1: 5.1k(J)  SIZECODESMD: 1608  (hidden comment: R)
R67  VAL1: 47k(J)  SIZECODESMD: 1608  (hidden comment: R)
R68  VAL1: 470(J)  SIZECODESMD: 1608  (hidden comment: R)
R69  VAL1: 5.1k(J)  SIZECODESMD: 1608  (hidden comment: R)
R70  VAL1: 47k(J)  SIZECODESMD: 1608  (hidden comment: R)
R71  VAL1: 5.1k(J)  SIZECODESMD: 1608  (hidden comment: R)
R72  VAL1: 10(J)  SIZECODESMD: 1608  (hidden comment: R)
R73  VAL1: 10k(J)  SIZECODESMD: 1608  (hidden comment: R)
R74  VAL1: 10k(J)  SIZECODESMD: 1608  (hidden comment: R)
R94  VAL1: 10(J)  SIZECODESMD: 1608  (hidden comment: R)
R95  VAL1: 10(J)  SIZECODESMD: 1608  (hidden comment: R)
R96  NOTMOUNT: NOT MOUNT  SIZECODESMD: 1608  (hidden comment: R)
R100  VAL1: 10(J)  SIZECODESMD: 1608  (hidden comment: R)
R101  VAL1: 10(J)  SIZECODESMD: 1608  (hidden comment: R)
R102  NOTMOUNT: NOT MOUNT  SIZECODESMD: 1608  (hidden comment: R)
R104  VAL1: 20(F)  SIZECODESMD: 1608  (hidden comment: R)
TP39  TP  (value not drawn)
TP43  TP  (value not drawn)
U?#3  DATE: 2026/09/14  DRAWINGNUMBER: RD258-SCHEMATIC2-01  TITLE: iXPLV(ｮ) SiC Module Gate Driver  FUNCTION: High-Side Gate Clamp  SHEETNUMBER: 3/10  REVISION: 01  (hidden comment: WAKU_DEF100)

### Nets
VN_1_A: C69.2 C70.2 C71.2 C72.2 C73.2 C74.2 C76.2 IC22.5 IC23.5 IC24.5 IC25.5 IC26.5 IC27.8 R66.2 R67.2
VN_6_VEE_A: C69.1 C70.1 C71.1 C72.1 C73.1 C74.1 C75.1 C76.1 C77.1 C78.1 D24.2(A) IC22.2 IC23.2 IC23.3 IC24.2 IC25.2 IC26.2 IC26.3 IC27.4 IC27.5(2A) IC27.6(2B) Q8.2(S) Q9.2(S) Q10.2(E) Q17.4 R71.1 R73.1 R74.1
GCLP_EN_A: IC25.1 IC27.2 ; off-sheet GCLP_EN_A
SIG0034: IC22.4 R72.1
SIG0039: C77.2 IC25.3 R69.2
SIG00085: C75.2 IC24.3 R68.1 R73.2
SIG00086: IC24.1 R66.1 R71.2
SIG00087: IC24.4 R70.2
SIG00089: C78.2 IC23.1 Q10.3(C) R67.1
SIG00092: IC22.1 IC27.7
SIG00096: D24.1(C) Q7.1(B) Q8.3(D) R65.1
SIG00097: Q9.1(G) R72.2 R74.2 TP39.1
SIG00098: Q7.2(E) R68.2
SIG00133: Q17.1 Q17.2 Q17.5 Q17.6 R100.1 R101.1 R102.1
SIG00134: Q17.3 R104.2
SIG00135: R94.1 R95.1 R96.1 R100.2 R101.2 R102.2
SIG00310: IC26.6 Q8.1(G)
SIG00311: IC25.4 IC26.1
SIG00312: IC23.6 IC27.1
SIG00313: IC25.6 R69.1
STO_VMOS_A: R104.1 TP43.1 ; off-sheet STO_VMOS_A
VGATE_A: Q7.3(C) Q9.3(D) R65.2 R94.2 R95.2 R96.2 ; off-sheet VGATE_A
NetQ10_1: Q10.1(B) R70.1

Not connected (* = marked no-connect by the designer): IC22 3; IC23 4; IC26 4; IC27 3(2Y)

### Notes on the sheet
- A/2
- (near IC27) 2/2
- (near IC25) 1/2
- 2/2
- 1/2

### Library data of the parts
C69-C78 = C: as C24 on sheet 1
D24 = CEZ5V6: TIME: 14:49:55; UPDATEUSER: fukuda-y; UPDATETIME: 08:16:22; SAVECOUNT: 9; SAVEAREA0: -4630,-153,17114,13055; PSPICETEMPLATE: X^@REFDES %C %A @MODEL; ORIGINALSYMBOLORIGIN: (0,0); INSTANCENAME: INS2262356
IC22 = TC7SZ04AFS: TIME: 11:55:02; UPDATEUSER: t5459927; UPDATETIME: 19:30:29; SAVECOUNT: 6; PSPICETEMPLATE: X^@REFDES %INA %GND %NC %OUTY %VCC @MODEL; OriginalSymbolOrigin: (0,-5080); INSTANCENAME: INS2262788
IC23 IC25 IC26 = TC7PZ14FU_2: TIME: 11:55:01; UPDATEUSER: t5459927; UPDATETIME: 19:09:34; SAVECOUNT: 7; SPLIT_INST: TRUE; PSPICETEMPLATE: X^@REFDES %1A %GND %2A %2Y %VCC %1Y @MODEL; SWAP_INFO: (S1+S2); OriginalSymbolOrigin: (5080,15240); CaptureCellPackProp: TC7PZ14FU_2A; FUNCN: TC7PZ14FU_1
IC24 = TC75S57FU: TIME: 08:48:15; UPDATEUSER: t5459927; UPDATETIME: 11:03:38; SAVECOUNT: 2; PSPICETEMPLATE: X^@REFDES %INN %VSS %INP %OUT %VDD @MODEL; OriginalSymbolOrigin: (2540,0); INSTANCENAME: INS2262824
IC27 = TC7WZ00FK_1: TIME: 08:52:39; UPDATEUSER: sptcae09; UPDATETIME: 16:09:46; SAVECOUNT: 9; SWAP_INFO: (S1+S2); ORDER: $pOrder; SPLIT_INST: TRUE; ・: 20mA; USER_VALUE: TC7W00FK; PSPICETEMPLATE: X^@REFDES %1A %1B %2Y %GND %2A %2B %1Y %VCC @MODEL; DESCRIPTION-A: NAND 2ch Logic; ORIGINALSYMBOLORIGIN: (2540,-2540); CaptureCellPackProp: TC7WZ00FK_1A
Q7 = 2SC5658J: TIME: 09:39:04; UPDATEUSER: 19910145; UPDATETIME: 15:12:10; SAVECOUNT: 8; VENDOR: ROHM; SAVEAREA0: -6194,-158,18648,15662; PSPICETEMPLATE: X^@REFDES %C %B %E @MODEL; ORIGINALSYMBOLORIGIN: (0,0); INSTANCENAME: INS2262598
Q8 = SSM3K15AFS: TIME: 08:48:15; UPDATEUSER: HP_Z8_KEYSHOT; SAVECOUNT: 2; ORIGINALSYMBOLORIGIN: (0,0); PSPICETEMPLATE: X^@REFDES %D %G %S @MODEL; INSTANCENAME: INS2262996
Q9 = SSM3K318R: TIME: 08:48:16; UPDATEUSER: HP_Z8_KEYSHOT; SAVECOUNT: 2; ORIGINALSYMBOLORIGIN: (0,0); PSPICETEMPLATE: X^@REFDES %D %G %S @MODEL; INSTANCENAME: INS2261964
Q10 = 2SC5658J: TIME: 09:39:04; UPDATEUSER: 19910145; UPDATETIME: 15:12:10; SAVECOUNT: 8; VENDOR: ROHM; SAVEAREA0: -6194,-158,18648,15662; PSPICETEMPLATE: X^@REFDES %C %B %E @MODEL; ORIGINALSYMBOLORIGIN: (0,0); INSTANCENAME: INS2262860
Q17 = SSM6K804R: TIME: 08:48:15; UPDATEUSER: HP_Z8_KEYSHOT; SAVECOUNT: 14; SAVEAREA0: -7120,-295,29516,23636; ORIGINALSYMBOLORIGIN: (0,0); PSPICETEMPLATE: X^@REFDES %1 %2 %3 %4 %5 %6 @MODEL; INSTANCENAME: INS2262956
R65-R71 R73 R74 R94 R95 R100 R101 R104 = R: as R187 on sheet 1
R72 = R: TIME: 08:48:13; UPDATEUSER: HP_Z8_KEYSHOT; SAVECOUNT: 2; VAL2: 100mW; TC1: 0; PSPICETEMPLATE: R^@REFDES %1 %2 ?TOLERANCE¦R^@REFDES¦ @VALUE TC=@TC1,@TC2 ?TOLERANCE¦\n.model R^@REFDES RES R=1 DEV=@TOLERANCE% TC1=@TC1 TC2=@TC2¦; ORIGINALSYMBOLORIGIN: (0,0); INSTANCENAME: INS2262084
R96 R102 = R: as R87 on sheet 2
TP39 = TP: TIME: 16:12:21; UPDATEUSER: fukuda-y; UPDATETIME: 16:18:11; SAVECOUNT: 2; SAVEAREA0: -242,-92,12810,7836; ORIGINALSYMBOLORIGIN: (0,0); INSTANCENAME: INS2262622
TP43 = TP: TIME: 16:12:21; UPDATEUSER: fukuda-y; UPDATETIME: 16:18:11; SAVECOUNT: 2; SAVEAREA0: -242,-92,12810,7836; ORIGINALSYMBOLORIGIN: (0,0); INSTANCENAME: INS2262916
U?#3 = WAKU_DEF100: PLOTTIME: HH:MM; SAVEAREA0: -63393,-16950,474261,314592; TIME: 14:30:25; UPDATEUSER: t5459927; UPDATETIME: 14:20:04; SAVECOUNT: 4; OriginalSymbolOrigin: (10160,284480); SHTSAVECOUNT: 29

## Sheet 4.SchDoc
size 420 x 297 mm
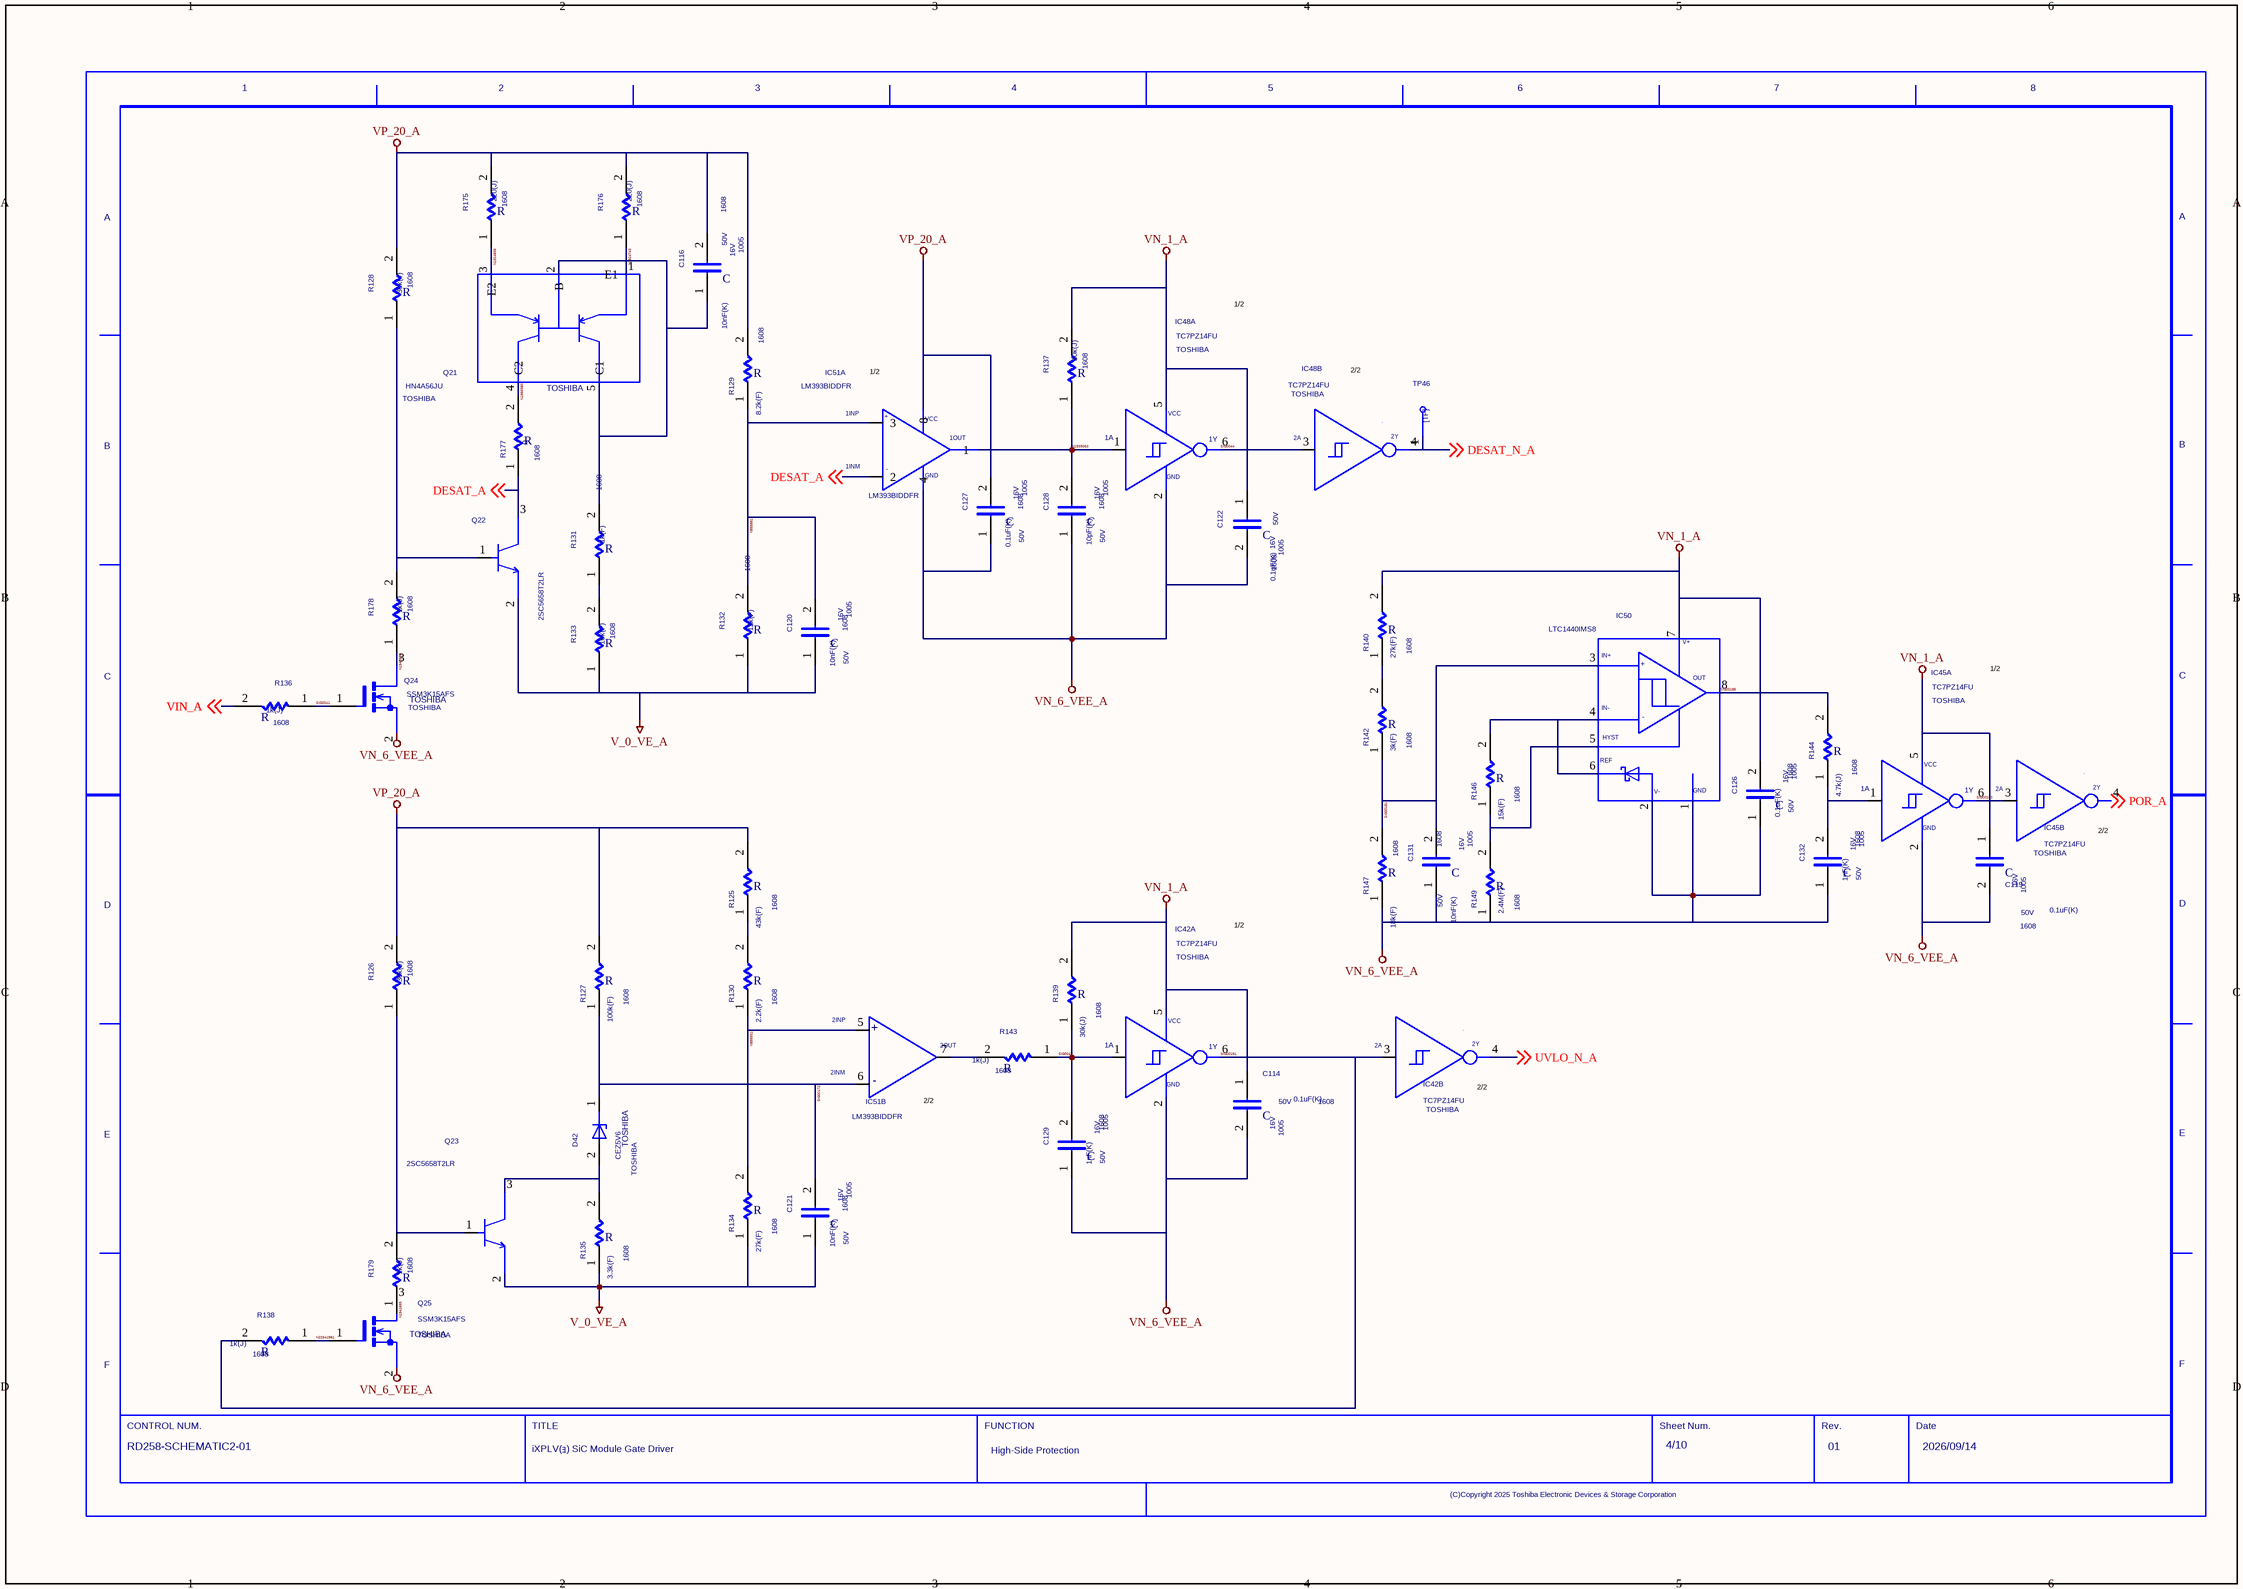
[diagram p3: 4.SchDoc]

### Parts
(Parts that share a designator on the sheet are numbered #1, #2 ... from top to bottom, then left to right.)
C114  VAL1: 0.1uF(K)  CODE: 1005  VOLTAGE: 16V  SIZECODESMD: 1608  VAL2: 50V  (hidden comment: C)
C116  VAL1: 10nF(K)  CODE: 1005  VOLTAGE: 16V  SIZECODESMD: 1608  VAL2: 50V  (hidden comment: C)
C119  VAL1: 0.1uF(K)  CODE: 1005  VOLTAGE: 16V  SIZECODESMD: 1608  VAL2: 50V  (hidden comment: C)
C120  VAL1: 10nF(K)  CODE: 1005  VOLTAGE: 16V  SIZECODESMD: 1608  VAL2: 50V  (hidden comment: C)
C121  VAL1: 10nF(K)  CODE: 1005  VOLTAGE: 16V  SIZECODESMD: 1608  VAL2: 50V  (hidden comment: C)
C122  VAL1: 0.1uF(K)  CODE: 1005  VOLTAGE: 16V  SIZECODESMD: 1608  VAL2: 50V  (hidden comment: C)
C126  VAL1: 0.1uF(K)  CODE: 1005  VOLTAGE: 16V  SIZECODESMD: 1608  VAL2: 50V  (hidden comment: C)
C127  VAL1: 0.1uF(K)  CODE: 1005  VOLTAGE: 16V  SIZECODESMD: 1608  VAL2: 50V  (hidden comment: C)
C128  VAL1: 10pF(K)  CODE: 1005  VOLTAGE: 16V  SIZECODESMD: 1608  VAL2: 50V  (hidden comment: C)
C129  VAL1: 1nF(K)  CODE: 1005  VOLTAGE: 16V  SIZECODESMD: 1608  VAL2: 50V  (hidden comment: C)
C131  VAL1: 10nF(K)  CODE: 1005  VOLTAGE: 16V  SIZECODESMD: 1608  VAL2: 50V  (hidden comment: C)
C132  VAL1: 1nF(K)  CODE: 1005  VOLTAGE: 16V  SIZECODESMD: 1608  VAL2: 50V  (hidden comment: C)
D42  VENDOR: TOSHIBA  (hidden comment: CEZ5V6)
IC42  USERCOMPTEXT3: TOSHIBA  VAL3: TC7PZ14FU  (hidden comment: TC7PZ17FU)  (parts A,B of 2)
IC45  USERCOMPTEXT3: TOSHIBA  VAL3: TC7PZ14FU  (hidden comment: TC7PZ17FU)  (parts A,B of 2)
IC48  USERCOMPTEXT3: TOSHIBA  VAL3: TC7PZ14FU  (hidden comment: TC7PZ17FU)  (parts A,B of 2)
IC50  VAL3: LTC1440IMS8  (hidden comment: LTC1440IS8)
IC51  VAL1: LM393BIDDFR  (hidden comment: LM393B_2)  (parts A,B of 2)
Q21  VENDOR: TOSHIBA  (hidden comment: HN4A56JU)
Q22  VAL3: 2SC5658T2LR  (hidden comment: 2SC5658J)
Q23  VAL3: 2SC5658T2LR  (hidden comment: 2SC5658J)
Q24  VENDOR: TOSHIBA  (hidden comment: SSM3K15AFS)
Q25  VENDOR: TOSHIBA  (hidden comment: SSM3K15AFS)
R125  VAL1: 43k(F)  SIZECODESMD: 1608  (hidden comment: R)
R126  VAL1: 30k(J)  SIZECODESMD: 1608  (hidden comment: R)
R127  VAL1: 100k(F)  SIZECODESMD: 1608  (hidden comment: R)
R128  VAL1: 30k(J)  SIZECODESMD: 1608  (hidden comment: R)
R129  VAL1: 8.2k(F)  SIZECODESMD: 1608  (hidden comment: R)
R130  VAL1: 2.2k(F)  SIZECODESMD: 1608  (hidden comment: R)
R131  VAL1: 1k(F)  SIZECODESMD: 1608  (hidden comment: R)
R132  VAL1: 12k(F)  SIZECODESMD: 1608  (hidden comment: R)
R133  VAL1: 10k(F)  SIZECODESMD: 1608  (hidden comment: R)
R134  VAL1: 27k(F)  SIZECODESMD: 1608  (hidden comment: R)
R135  VAL1: 3.3k(F)  SIZECODESMD: 1608  (hidden comment: R)
R136  VAL1: 1k(J)  SIZECODESMD: 1608  (hidden comment: R)
R137  VAL1: 30k(J)  SIZECODESMD: 1608  (hidden comment: R)
R138  VAL1: 1k(J)  SIZECODESMD: 1608  (hidden comment: R)
R139  VAL1: 30k(J)  SIZECODESMD: 1608  (hidden comment: R)
R140  VAL1: 27k(F)  SIZECODESMD: 1608  (hidden comment: R)
R142  VAL1: 3k(F)  SIZECODESMD: 1608  (hidden comment: R)
R143  VAL1: 1k(J)  SIZECODESMD: 1608  (hidden comment: R)
R144  VAL1: 4.7k(J)  SIZECODESMD: 1608  (hidden comment: R)
R146  VAL1: 15k(F)  SIZECODESMD: 1608  (hidden comment: R)
R147  VAL1: 18k(F)  SIZECODESMD: 1608  (hidden comment: R)
R149  VAL1: 2.4M(F)  SIZECODESMD: 1608  (hidden comment: R)
R175  VAL1: 220(J)  SIZECODESMD: 1608  (hidden comment: R)
R176  VAL1: 220(J)  SIZECODESMD: 1608  (hidden comment: R)
R177  VAL1: 0  SIZECODESMD: 1608  (hidden comment: R)
R178  VAL1: 1k(J)  SIZECODESMD: 1608  (hidden comment: R)
R179  VAL1: 1k(J)  SIZECODESMD: 1608  (hidden comment: R)
TP46  TP  (value not drawn)
U?#4  DATE: 2026/09/14  DRAWINGNUMBER: RD258-SCHEMATIC2-01  TITLE: iXPLV(ｮ) SiC Module Gate Driver  FUNCTION: High-Side Protection  SHEETNUMBER: 4/10  REVISION: 01  (hidden comment: WAKU_DEF100)

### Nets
V_0_VE_A: C120.1 C121.1 Q22.2(E) Q23.2(E) R132.1 R133.1 R134.1 R135.1
VN_1_A: C114.1 C119.1 C122.1 C126.2 IC42.5 IC45.5 IC48.5 IC50.7(V+) R137.2 R139.2 R140.2
VN_6_VEE_A: C114.2 C119.2 C122.2 C126.1 C127.1 C128.1 C129.1 C131.1 C132.1 IC42.2 IC45.2 IC48.2 IC50.1(GND) IC50.2(V-) IC51.4 Q24.2(S) Q25.2(S) R147.1 R149.1
VP_20_A: C116.2 C127.2 IC51.8 R125.2 R126.2 R127.2 R128.2 R129.2 R175.2 R176.2
DESAT_A: IC51.2 Q22.3(C) R177.1 ; off-sheet DESAT_A
DESAT_N_A: IC48.4 TP46.1 ; off-sheet DESAT_N_A
N855881: C120.2 IC51.3 R129.1 R132.2
N855931: IC51.5 R130.1 R134.2
N1924743: Q21.1(E1) R176.1
N1924835: Q21.3(E2) R175.1
N1939063: C128.2 IC48.1 IC51.1 R137.1
N1941594: Q24.3(D) R178.1
N1941665: Q25.3(D) R179.1
N1966980: Q21.4(C2) R177.2
N22641981: Q25.1(G) R138.1
POR_A: IC45.4 ; off-sheet POR_A
SIG0041: Q24.1(G) R136.1
SIG0043: C129.2 IC42.1 R139.1 R143.1
SIG0044: IC48.3 IC48.6
SIG00166: Q22.1(B) R128.1 R178.2
SIG00167: C116.1 Q21.2(B) Q21.5(C1) R131.2
SIG00168: R131.1 R133.2
SIG00170: Q23.1(B) R126.1 R179.2
SIG00171: D42.2(A) Q23.3(C) R135.2
SIG00172: C121.2 D42.1(C) IC51.6 R127.1
SIG00173: R125.1 R130.2
SIG00178: IC51.7 R143.2
SIG00180: R140.1 R142.2
SIG00181: C131.2 IC50.3(IN+) R142.1 R147.2
SIG00182: IC50.4(IN-) IC50.6(REF) R146.2
SIG00183: IC50.5(HYST) R146.1 R149.2
SIG00185: IC50.8(OUT) R144.2
SIG00186: C132.2 IC45.1 R144.1
SIG00191: IC42.3 IC42.6 R138.2
SIG00193: IC45.3 IC45.6
UVLO_N_A: IC42.4 ; off-sheet UVLO_N_A
VIN_A: R136.2 ; off-sheet VIN_A

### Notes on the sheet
- 1/2
- (near IC51) 1/2
- 2/2
- (near IC45) 2/2
- (near IC51) 2/2
- (near IC42) 2/2

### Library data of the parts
C114 C116 C119-C122 C126-C129 C131 C132 = C: as C24 on sheet 1
D42 = CEZ5V6: TIME: 14:49:55; UPDATEUSER: fukuda-y; UPDATETIME: 08:16:22; SAVECOUNT: 9; SAVEAREA0: -4630,-153,17114,13055; PSPICETEMPLATE: X^@REFDES %C %A @MODEL; ORIGINALSYMBOLORIGIN: (0,0); INSTANCENAME: INS2265024
IC42 IC45 IC48 = TC7PZ14FU_2: as IC44 on sheet 1
IC50 = LTC1440IS8: TIME: 08:48:16; UPDATEUSER: t5459927; UPDATETIME: 17:22:21; SAVECOUNT: 4; PSPICETEMPLATE: X^@REFDES %GND %V- %IN+ %IN- %HYST %REF %V+ %OUT @MODEL; OriginalSymbolOrigin: (0,0); INSTANCENAME: INS2264292
IC51 = LM393B_2: TIME: 08:48:12; UPDATEUSER: t5459927; UPDATETIME: 19:15:42; SAVECOUNT: 5; SPLIT_INST: TRUE; PSPICETEMPLATE: X^@REFDES %INN %VSS %INP %OUT %VDD @MODEL; COMP: LM393B; VENDOR: TI; SWAP_INFO: (S1+S2); OriginalSymbolOrigin: (2540,0); CaptureCellPackProp: LM393B_2A; FUNCN: LM393B_1; INSTANCENAME: INS2264892
Q21 = HN4A56JU: TIME: 08:48:13; UPDATEUSER: HP_Z8_KEYSHOT; SAVECOUNT: 2; PSPICETEMPLATE: X^@REFDES %B1 %E %B2 %C2 %C1 @MODEL; OriginalSymbolOrigin: (0,0); INSTANCENAME: INS2265108
Q22 = 2SC5658J: TIME: 09:39:04; UPDATEUSER: 19910145; UPDATETIME: 15:12:10; SAVECOUNT: 8; VENDOR: ROHM; SAVEAREA0: -6194,-158,18648,15662; PSPICETEMPLATE: X^@REFDES %C %B %E @MODEL; ORIGINALSYMBOLORIGIN: (0,0); INSTANCENAME: INS2264212
Q23 = 2SC5658J: TIME: 09:39:04; UPDATEUSER: 19910145; UPDATETIME: 15:12:10; SAVECOUNT: 8; VENDOR: ROHM; SAVEAREA0: -6194,-158,18648,15662; PSPICETEMPLATE: X^@REFDES %C %B %E @MODEL; ORIGINALSYMBOLORIGIN: (0,0); INSTANCENAME: INS2264508
Q24 = SSM3K15AFS: TIME: 08:48:15; UPDATEUSER: HP_Z8_KEYSHOT; SAVECOUNT: 2; ORIGINALSYMBOLORIGIN: (0,0); PSPICETEMPLATE: X^@REFDES %D %G %S @MODEL; INSTANCENAME: INS2265300
Q25 = SSM3K15AFS: TIME: 08:48:15; UPDATEUSER: HP_Z8_KEYSHOT; SAVECOUNT: 2; ORIGINALSYMBOLORIGIN: (0,0); PSPICETEMPLATE: X^@REFDES %D %G %S @MODEL; INSTANCENAME: INS2264184
R125-R140 R142-R144 R146 R147 R149 R175 R176 R178 R179 = R: as R187 on sheet 1
R177 = R: TIME: 08:48:13; UPDATEUSER: HP_Z8_KEYSHOT; SAVECOUNT: 2; VAL2: 0.125; PSPICETEMPLATE: R^@REFDES %1 %2 ?TOLERANCE¦R^@REFDES¦ @VALUE TC=@TC1,@TC2 ?TOLERANCE¦\n.model R^@REFDES RES R=1 DEV=@TOLERANCE% TC1=@TC1 TC2=@TC2¦; ORIGINALSYMBOLORIGIN: (0,0); INSTANCENAME: INS2264424
TP46 = TP: TIME: 16:12:21; UPDATEUSER: fukuda-y; UPDATETIME: 16:18:11; SAVECOUNT: 2; SAVEAREA0: -242,-92,12810,7836; ORIGINALSYMBOLORIGIN: (0,0); INSTANCENAME: INS2264820
U?#4 = WAKU_DEF100: PLOTTIME: HH:MM; SAVEAREA0: -63393,-16950,474261,314592; TIME: 14:30:25; UPDATEUSER: t5459927; UPDATETIME: 14:21:06; SAVECOUNT: 4; OriginalSymbolOrigin: (10160,284480); SHTSAVECOUNT: 36

## Sheet 5.SchDoc
size 420 x 297 mm
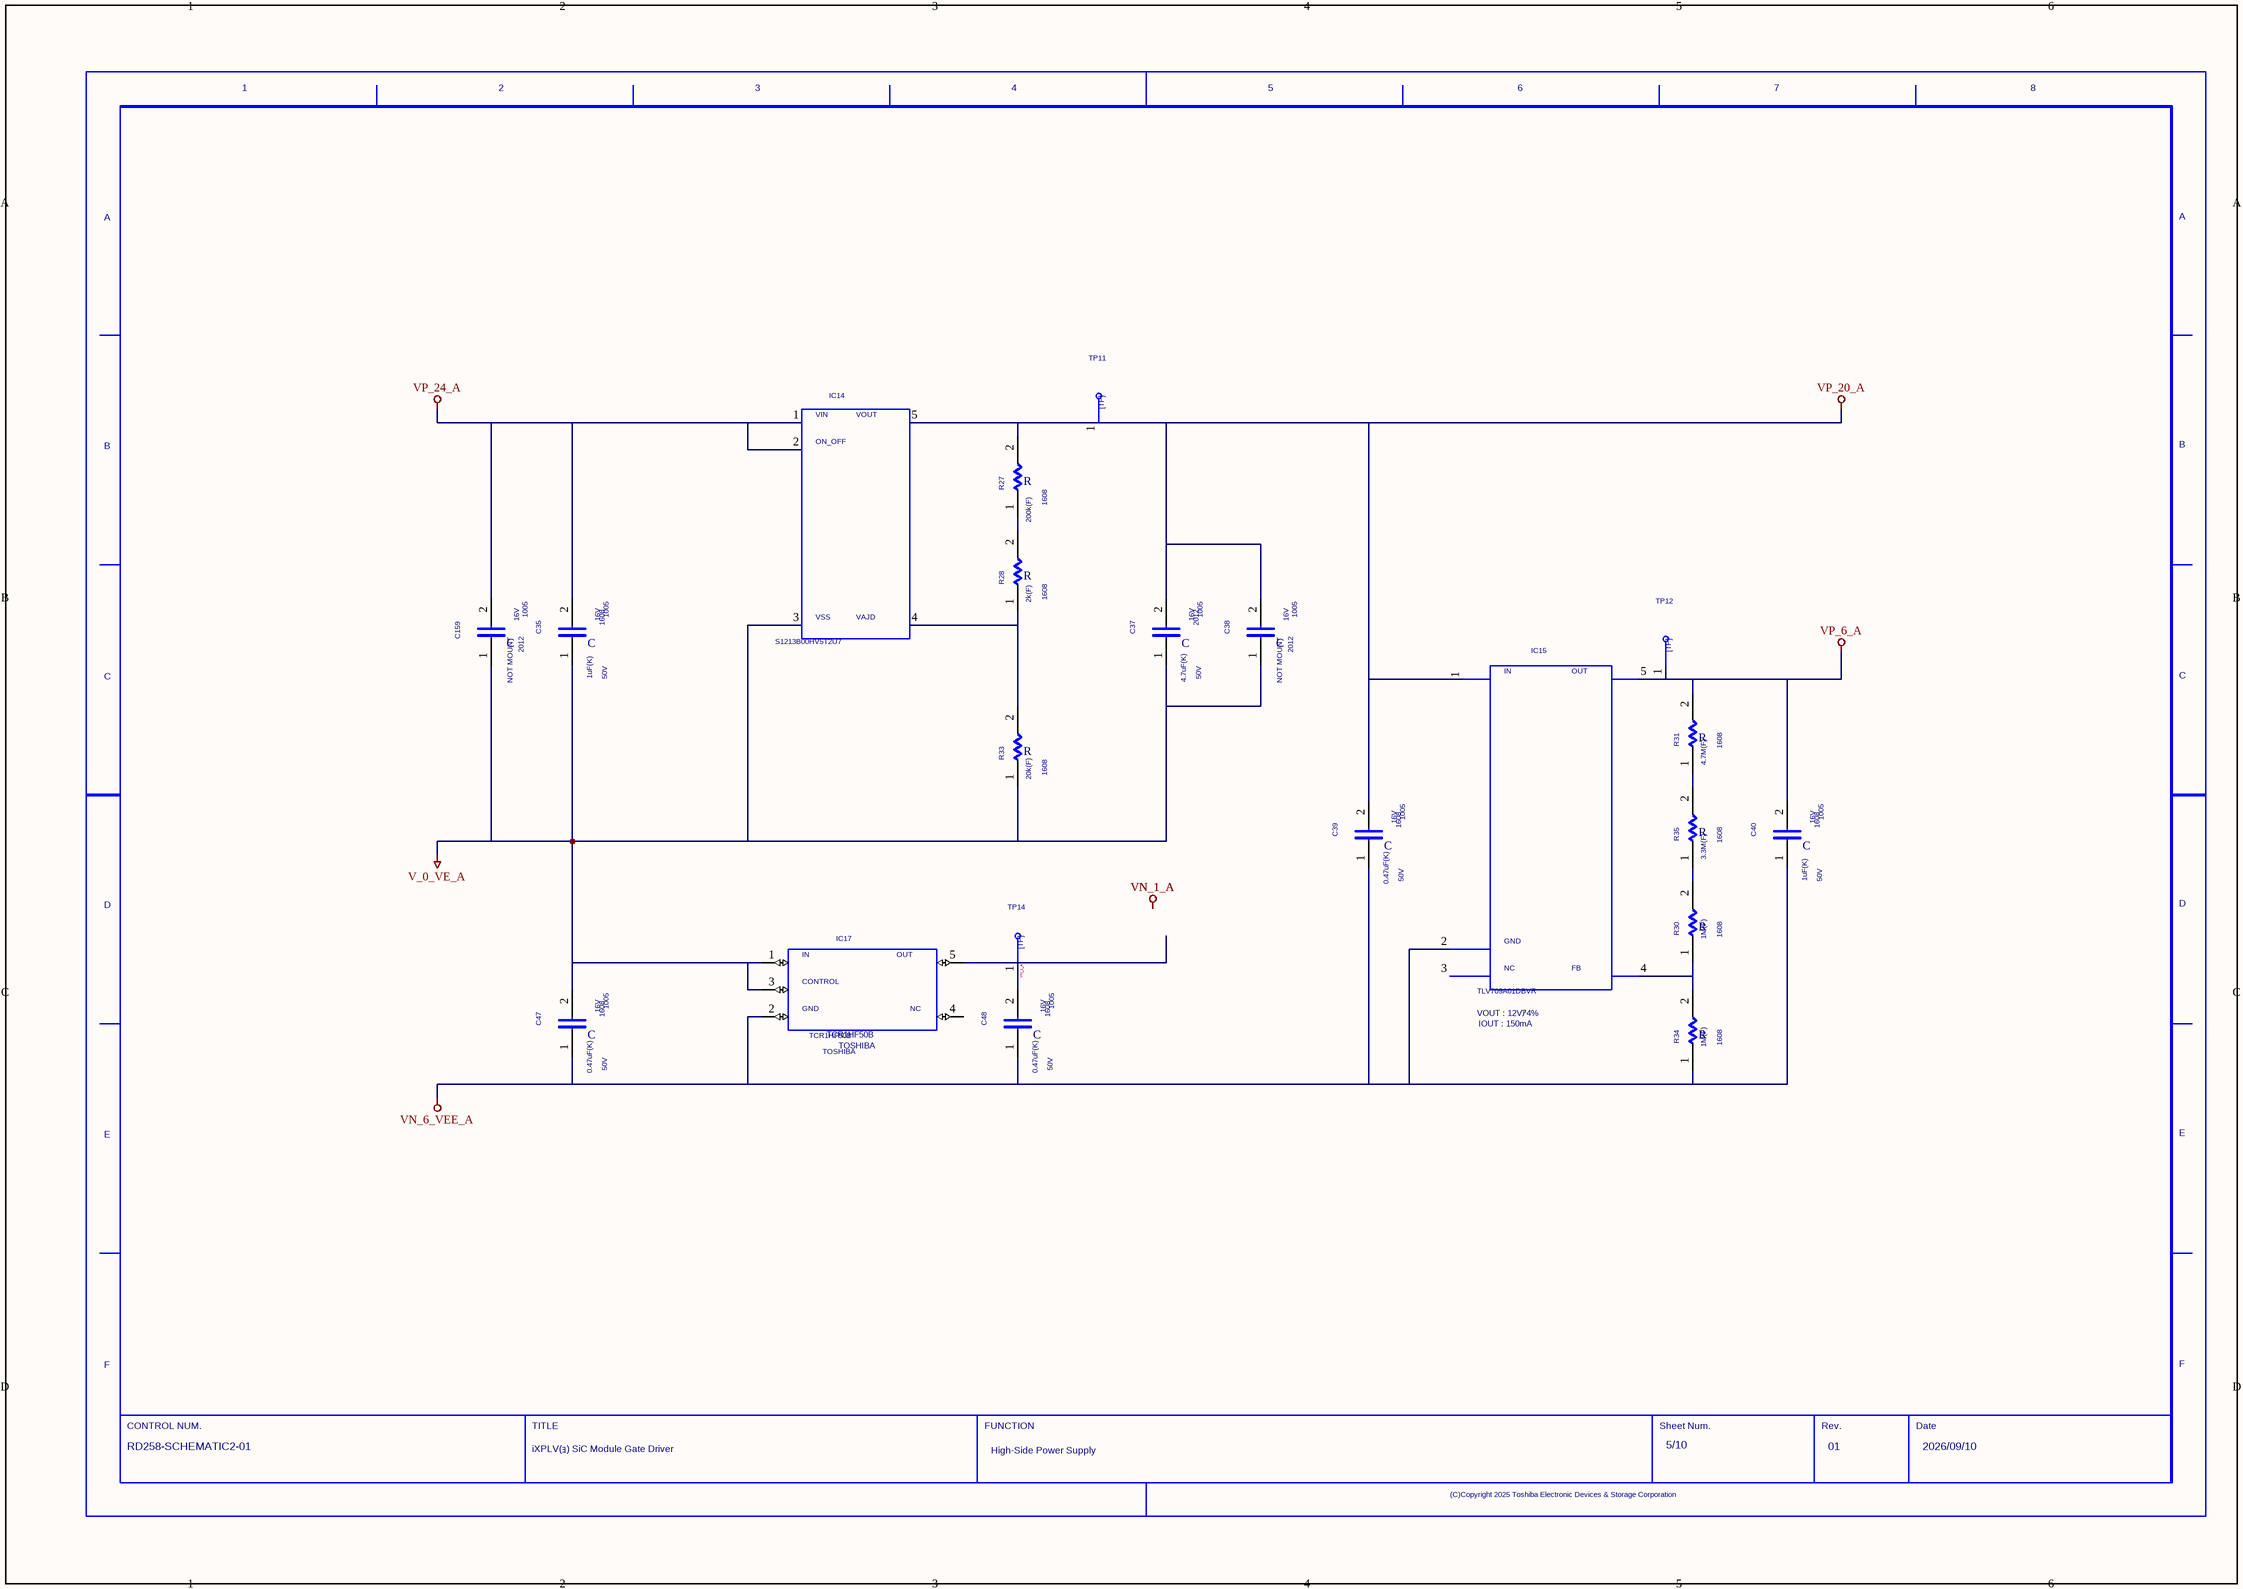
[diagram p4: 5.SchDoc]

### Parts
(Parts that share a designator on the sheet are numbered #1, #2 ... from top to bottom, then left to right.)
C35  VAL1: 1uF(K)  CODE: 1005  VOLTAGE: 16V  SIZECODESMD: 1608  VAL2: 50V  (hidden comment: C)
C37  VAL1: 4.7uF(K)  CODE: 1005  VOLTAGE: 16V  SIZECODESMD: 2012  VAL2: 50V  (hidden comment: C)
C38  CODE: 1005  VOLTAGE: 16V  NOTMOUNT: NOT MOUNT  SIZECODESMD: 2012  (hidden comment: C)
C39  VAL1: 0.47uF(K)  CODE: 1005  VOLTAGE: 16V  SIZECODESMD: 1608  VAL2: 50V  (hidden comment: C)
C40  VAL1: 1uF(K)  CODE: 1005  VOLTAGE: 16V  SIZECODESMD: 1608  VAL2: 50V  (hidden comment: C)
C47  VAL1: 0.47uF(K)  CODE: 1005  VOLTAGE: 16V  SIZECODESMD: 1608  VAL2: 50V  (hidden comment: C)
C48  VAL1: 0.47uF(K)  CODE: 1005  VOLTAGE: 16V  SIZECODESMD: 1608  VAL2: 50V  (hidden comment: C)
C159  CODE: 1005  VOLTAGE: 16V  NOTMOUNT: NOT MOUNT  SIZECODESMD: 2012  (hidden comment: C)
IC14  S1213B00HV5T2U7
IC15  NC: VOUT : 12Vｱ4%  CLASS: IOUT : 150mA  VAL3: TLV709A01DBVR  (hidden comment: TLV709)
IC17  TCR1HF50B  VENDOR: TOSHIBA
R27  VAL1: 200k(F)  SIZECODESMD: 1608  (hidden comment: R)
R28  VAL1: 2k(F)  SIZECODESMD: 1608  (hidden comment: R)
R30  VAL1: 1M(F)  SIZECODESMD: 1608  (hidden comment: R)
R31  VAL1: 4.7M(F)  SIZECODESMD: 1608  (hidden comment: R)
R33  VAL1: 20k(F)  SIZECODESMD: 1608  (hidden comment: R)
R34  VAL1: 1M(F)  SIZECODESMD: 1608  (hidden comment: R)
R35  VAL1: 3.3M(F)  SIZECODESMD: 1608  (hidden comment: R)
TP11  TP  (value not drawn)
TP12  TP  (value not drawn)
TP14  TP  (value not drawn)
U?#5  DATE: 2026/09/10  DRAWINGNUMBER: RD258-SCHEMATIC2-01  TITLE: iXPLV(ｮ) SiC Module Gate Driver  FUNCTION: High-Side Power Supply  SHEETNUMBER: 5/10  REVISION: 01  (hidden comment: WAKU_DEF100)

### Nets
V_0_VE_A: C35.1 C37.1 C38.1 C47.2 C159.1 IC14.3 IC17.1 IC17.3 R33.1
VN_1_A: C48.2 IC17.5 TP14.1
VN_6_VEE_A: C39.1 C40.1 C47.1 C48.1 IC15.2 IC17.2 R34.1
VP_6_A: C40.2 IC15.5 R31.2 TP12.1
VP_20_A: C37.2 C38.2 C39.2 IC14.5 IC15.1 R27.2 TP11.1
VP_24_A: C35.2 C159.2 IC14.1 IC14.2
SIG00045: R27.1 R28.2
SIG00046: IC14.4 R28.1 R33.2
SIG00047: IC15.4 R30.1 R34.2
SIG00048: R30.2 R35.1
SIG00049: R31.1 R35.2

Not connected (* = marked no-connect by the designer): IC15 3; IC17 4

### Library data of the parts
C35 C37-C40 C47 C48 C159 = C: as C91 on sheet 2
IC14 = S1213B00HV5T2U7: TIME: 08:48:13; UPDATEUSER: t5459927; UPDATETIME: 09:48:38; SAVECOUNT: 7; PSPICETEMPLATE: X^@REFDES %ADJUST %OUTPUT %INPUT @MODEL; OriginalSymbolOrigin: (0,0); INSTANCENAME: INS2266489
IC15 = TLV709: TIME: 08:48:16; UPDATEUSER: t5459927; UPDATETIME: 10:01:49; SAVECOUNT: 5; PSPICETEMPLATE: X^@REFDES %IN %GND %NC %FB %OUT @MODEL; OriginalSymbolOrigin: (0,0); INSTANCENAME: INS2266385
IC17 = TCR1HF50B: TIME: 11:54:59; UPDATEUSER: t5459927; UPDATETIME: 10:27:35; SAVECOUNT: 4; PSPICETEMPLATE: X^@REFDES %IN %GND %CONTROL %NC %OUT @MODEL; OriginalSymbolOrigin: (-2540,0); INSTANCENAME: INS2266087
R27 R28 R30 R31 R33-R35 = R: as R89 on sheet 2
TP11 = TP: TIME: 16:12:21; UPDATEUSER: fukuda-y; UPDATETIME: 16:18:11; SAVECOUNT: 2; SAVEAREA0: -242,-92,12810,7836; ORIGINALSYMBOLORIGIN: (0,0); INSTANCENAME: INS2266317
TP12 = TP: TIME: 16:12:21; UPDATEUSER: fukuda-y; UPDATETIME: 16:18:11; SAVECOUNT: 2; SAVEAREA0: -242,-92,12810,7836; ORIGINALSYMBOLORIGIN: (0,0); INSTANCENAME: INS2266305
TP14 = TP: TIME: 16:12:21; UPDATEUSER: fukuda-y; UPDATETIME: 16:18:11; SAVECOUNT: 2; SAVEAREA0: -242,-92,12810,7836; ORIGINALSYMBOLORIGIN: (0,0); INSTANCENAME: INS2266293
U?#5 = WAKU_DEF100: PLOTTIME: HH:MM; SAVEAREA0: -63393,-16950,474261,314592; TIME: 14:30:25; UPDATEUSER: t5459927; UPDATETIME: 14:21:06; SAVECOUNT: 4; OriginalSymbolOrigin: (10160,284480); SHTSAVECOUNT: 24

## Sheet 6.SchDoc
size 420 x 297 mm
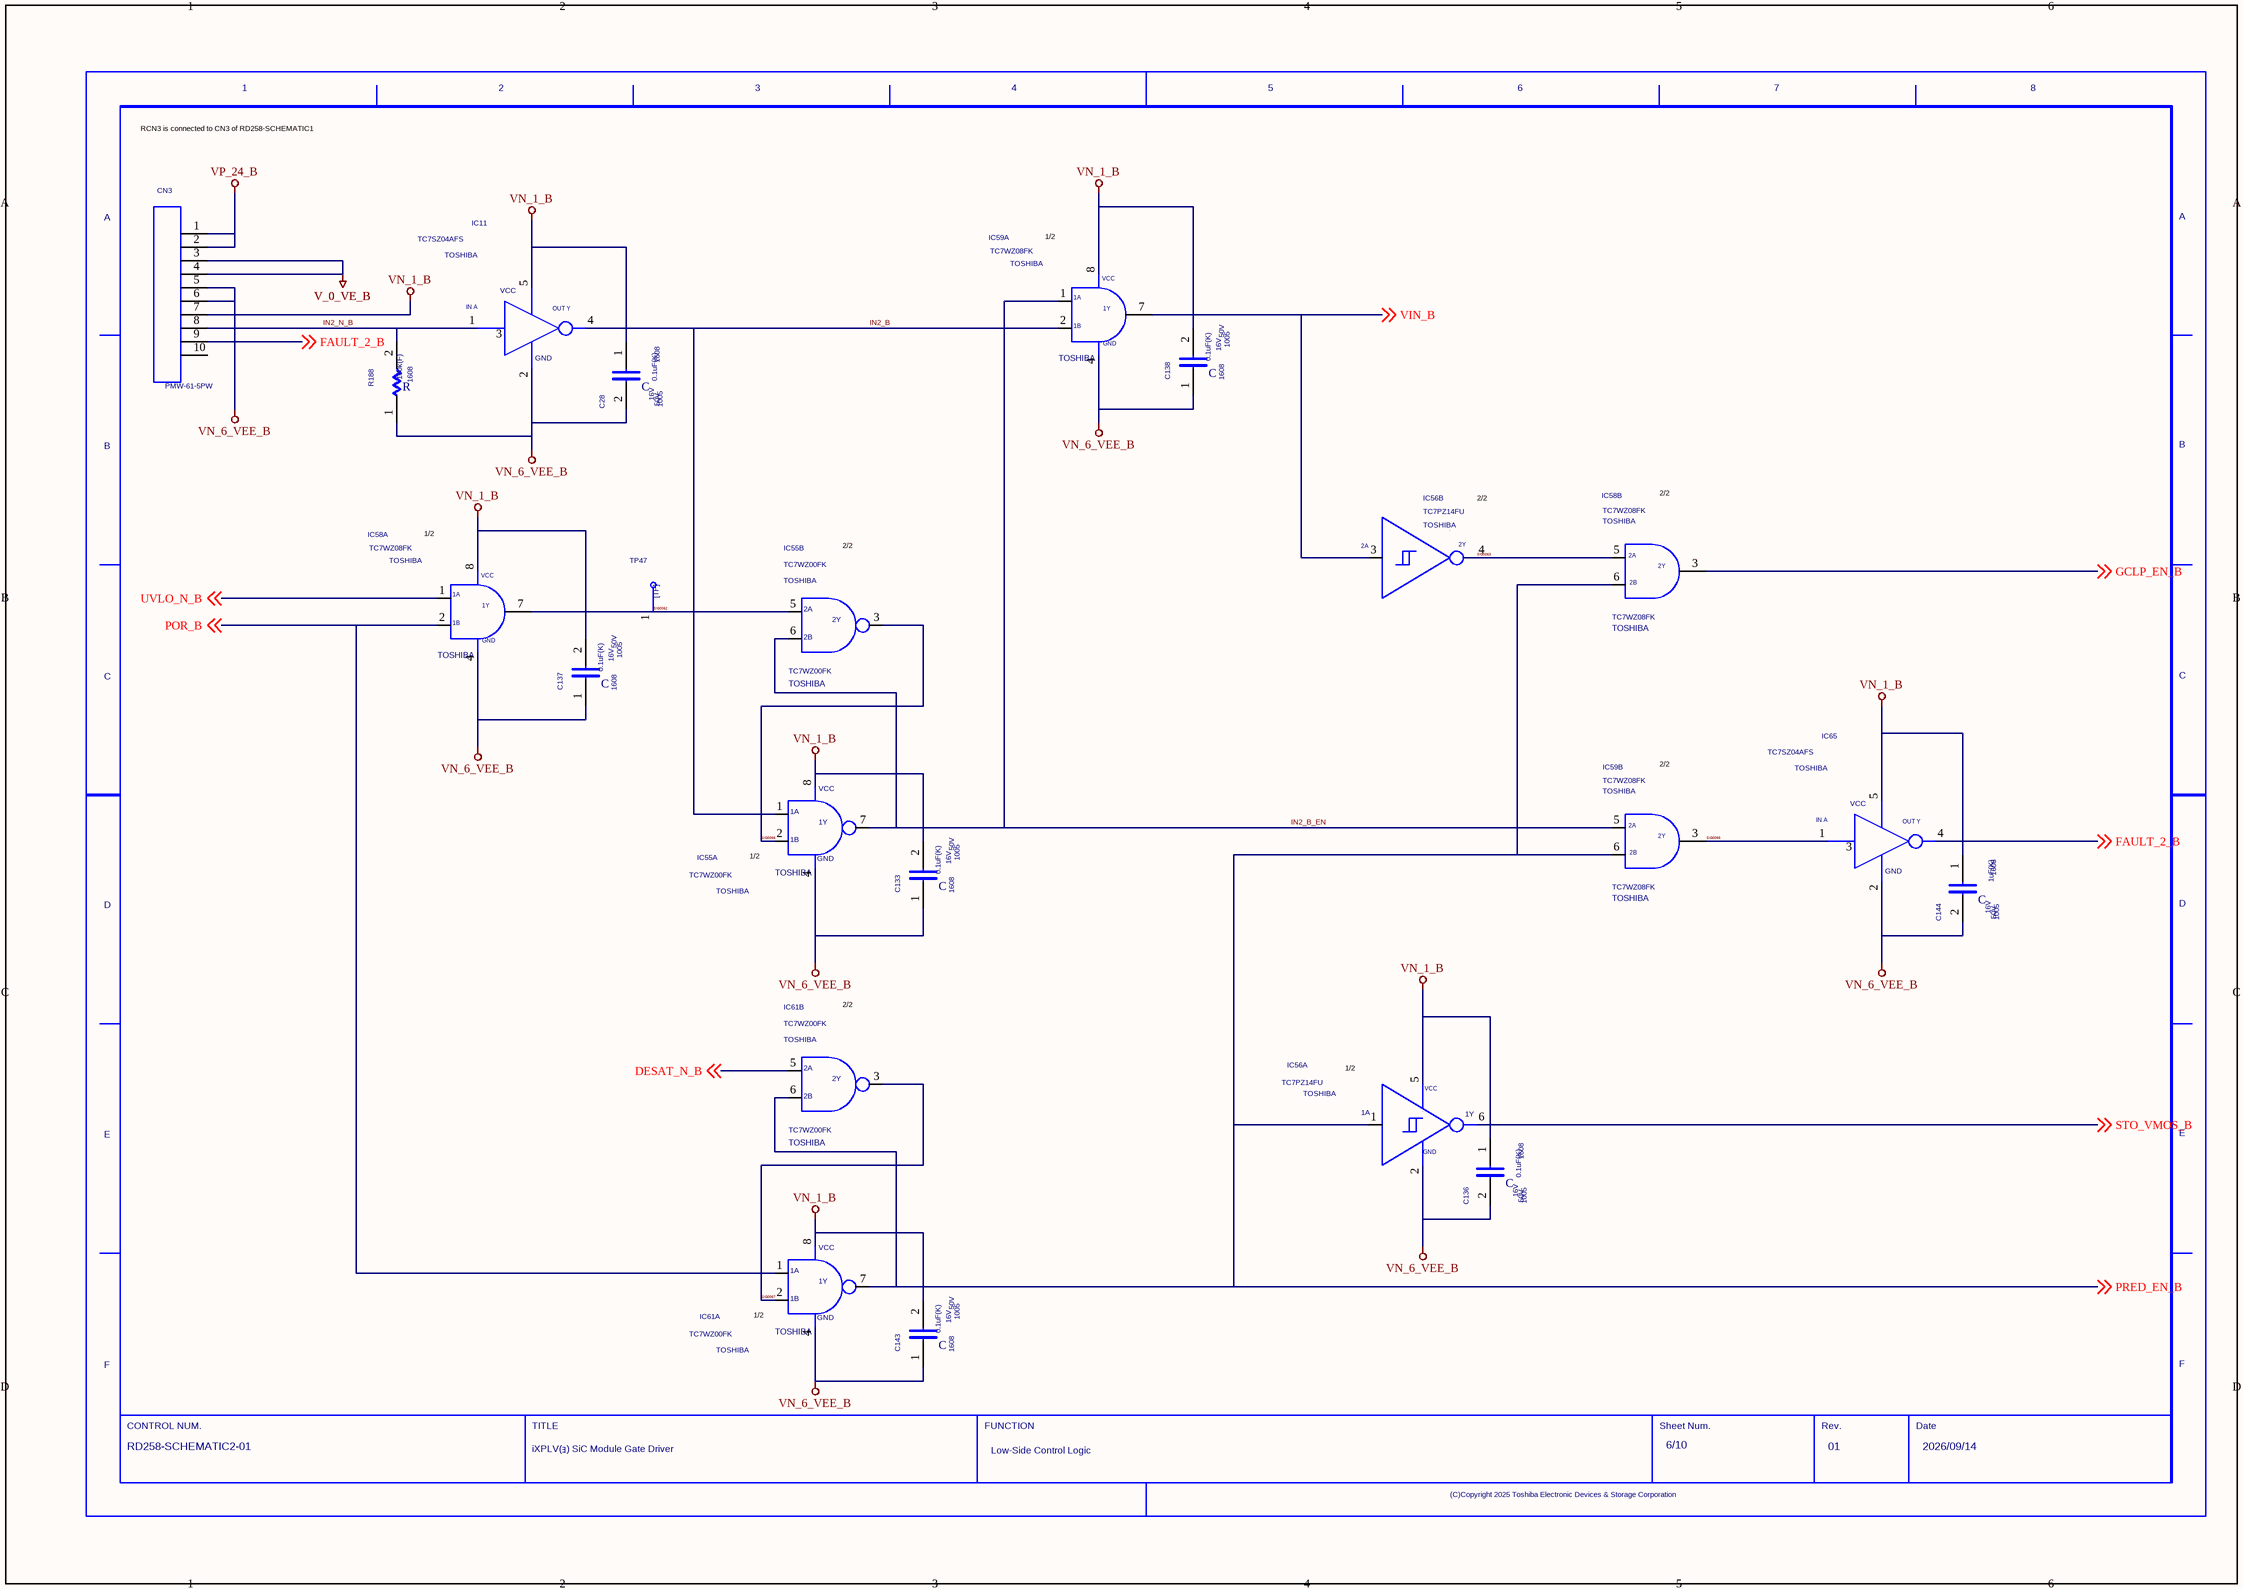
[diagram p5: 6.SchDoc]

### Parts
(Parts that share a designator on the sheet are numbered #1, #2 ... from top to bottom, then left to right.)
C28  VAL1: 0.1uF(K)  CODE: 1005  VOLTAGE: 16V  SIZECODESMD: 1608  VAL2: 50V  (hidden comment: C)
C133  VAL1: 0.1uF(K)  CODE: 1005  VOLTAGE: 16V  SIZECODESMD: 1608  VAL2: 50V  (hidden comment: C)
C136  VAL1: 0.1uF(K)  CODE: 1005  VOLTAGE: 16V  SIZECODESMD: 1608  VAL2: 50V  (hidden comment: C)
C137  VAL1: 0.1uF(K)  CODE: 1005  VOLTAGE: 16V  SIZECODESMD: 1608  VAL2: 50V  (hidden comment: C)
C138  VAL1: 0.1uF(K)  CODE: 1005  VOLTAGE: 16V  SIZECODESMD: 1608  VAL2: 50V  (hidden comment: C)
C143  VAL1: 0.1uF(K)  CODE: 1005  VOLTAGE: 16V  SIZECODESMD: 1608  VAL2: 50V  (hidden comment: C)
C144  VAL1: 1uF(K)  CODE: 1005  VOLTAGE: 16V  SIZECODESMD: 1608  VAL2: 50V  (hidden comment: C)
CN3  VAL3: PMW-61-5PW  (hidden comment: CN9_2)
IC11  USERCOMPTEXT3: TOSHIBA  (hidden comment: TC7SZ04AFS)
IC55  VENDOR: TOSHIBA  (hidden comment: TC7WZ00FK)  (parts A,B of 2)
IC56  USERCOMPTEXT3: TOSHIBA  VAL3: TC7PZ14FU  (hidden comment: TC7PZ17FU)  (parts A,B of 2)
IC58  VENDOR: TOSHIBA  (hidden comment: TC7WZ08FK)  (parts A,B of 2)
IC59  VENDOR: TOSHIBA  (hidden comment: TC7WZ08FK)  (parts A,B of 2)
IC61  VENDOR: TOSHIBA  (hidden comment: TC7WZ00FK)  (parts A,B of 2)
IC65  USERCOMPTEXT3: TOSHIBA  (hidden comment: TC7SZ04AFS)
R188  VAL1: 100k(F)  SIZECODESMD: 1608  (hidden comment: R)
TP47  TP  (value not drawn)
U?#6  DATE: 2026/09/14  DRAWINGNUMBER: RD258-SCHEMATIC2-01  TITLE: iXPLV(ｮ) SiC Module Gate Driver  FUNCTION: Low-Side Control Logic  SHEETNUMBER: 6/10  REVISION: 01  (hidden comment: WAKU_DEF100)

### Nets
V_0_VE_B: CN3.3 CN3.4
VN_1_B: C28.1 C133.2 C136.1 C137.2 C138.2 C143.2 C144.1 CN3.7 IC11.5 IC55.8 IC56.5 IC58.8 IC59.8 IC61.8 IC65.5
VN_6_VEE_B: C28.2 C133.1 C136.2 C137.1 C138.1 C143.1 C144.2 CN3.5 CN3.6 IC11.2 IC55.4 IC56.2 IC58.4 IC59.4 IC61.4 IC65.2 R188.1
VP_24_B: CN3.1 CN3.2
DESAT_N_B: IC61.5(2A) ; off-sheet DESAT_N_B
FAULT_2_B: CN3.9 IC65.4 ; off-sheet FAULT_2_B
GCLP_EN_B: IC58.3 ; off-sheet GCLP_EN_B
IN2_B: IC11.4 IC55.1 IC59.2
IN2_B_EN: IC55.6(2B) IC55.7 IC59.1 IC59.5
IN2_N_B: CN3.8 IC11.1 R188.2
POR_B: IC58.2 IC61.1 ; off-sheet POR_B
PRED_EN_B: IC56.1 IC58.6 IC59.6 IC61.6(2B) IC61.7 ; off-sheet PRED_EN_B
SIG0062: IC55.5(2A) IC58.7 TP47.1
SIG0063: IC56.4 IC58.5
SIG0065: IC59.3 IC65.1
SIG0066: IC55.2 IC55.3(2Y)
SIG0067: IC61.2 IC61.3(2Y)
STO_VMOS_B: IC56.6 ; off-sheet STO_VMOS_B
UVLO_N_B: IC58.1 ; off-sheet UVLO_N_B
VIN_B: IC56.3 IC59.7 ; off-sheet VIN_B

Not connected (* = marked no-connect by the designer): CN3 10; IC11 3; IC65 3

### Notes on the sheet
- RCN3 is connected to CN3 of RD258-SCHEMATIC1
- (near IC59) 1/2
- 2/2
- (near IC58) 1/2
- (near IC55) 1/2
- (near IC56) 1/2
- (near IC61) 1/2

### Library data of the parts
C28 C133 C136-C138 C143 C144 = C: as C24 on sheet 1
CN3 = CN10_1: as CN2 on sheet 1
IC11 IC65 = TC7SZ04AFS: as IC7 on sheet 1
IC55 IC61 = TC7WZ00FK_1: as IC43 on sheet 1
IC56 = TC7PZ14FU_2: as IC44 on sheet 1
IC58 IC59 = TC7WZ08FK_1: as IC46 on sheet 1
R188 = R: as R187 on sheet 1
TP47 = TP: as TP45 on sheet 1
U?#6 = WAKU_DEF100: PLOTTIME: HH:MM; SAVEAREA0: -63393,-16950,474261,314592; TIME: 14:30:25; UPDATEUSER: t5459927; UPDATETIME: 14:41:21; SAVECOUNT: 4; OriginalSymbolOrigin: (10160,284480); SHTSAVECOUNT: 36

## Sheet 7.SchDoc
size 420 x 297 mm
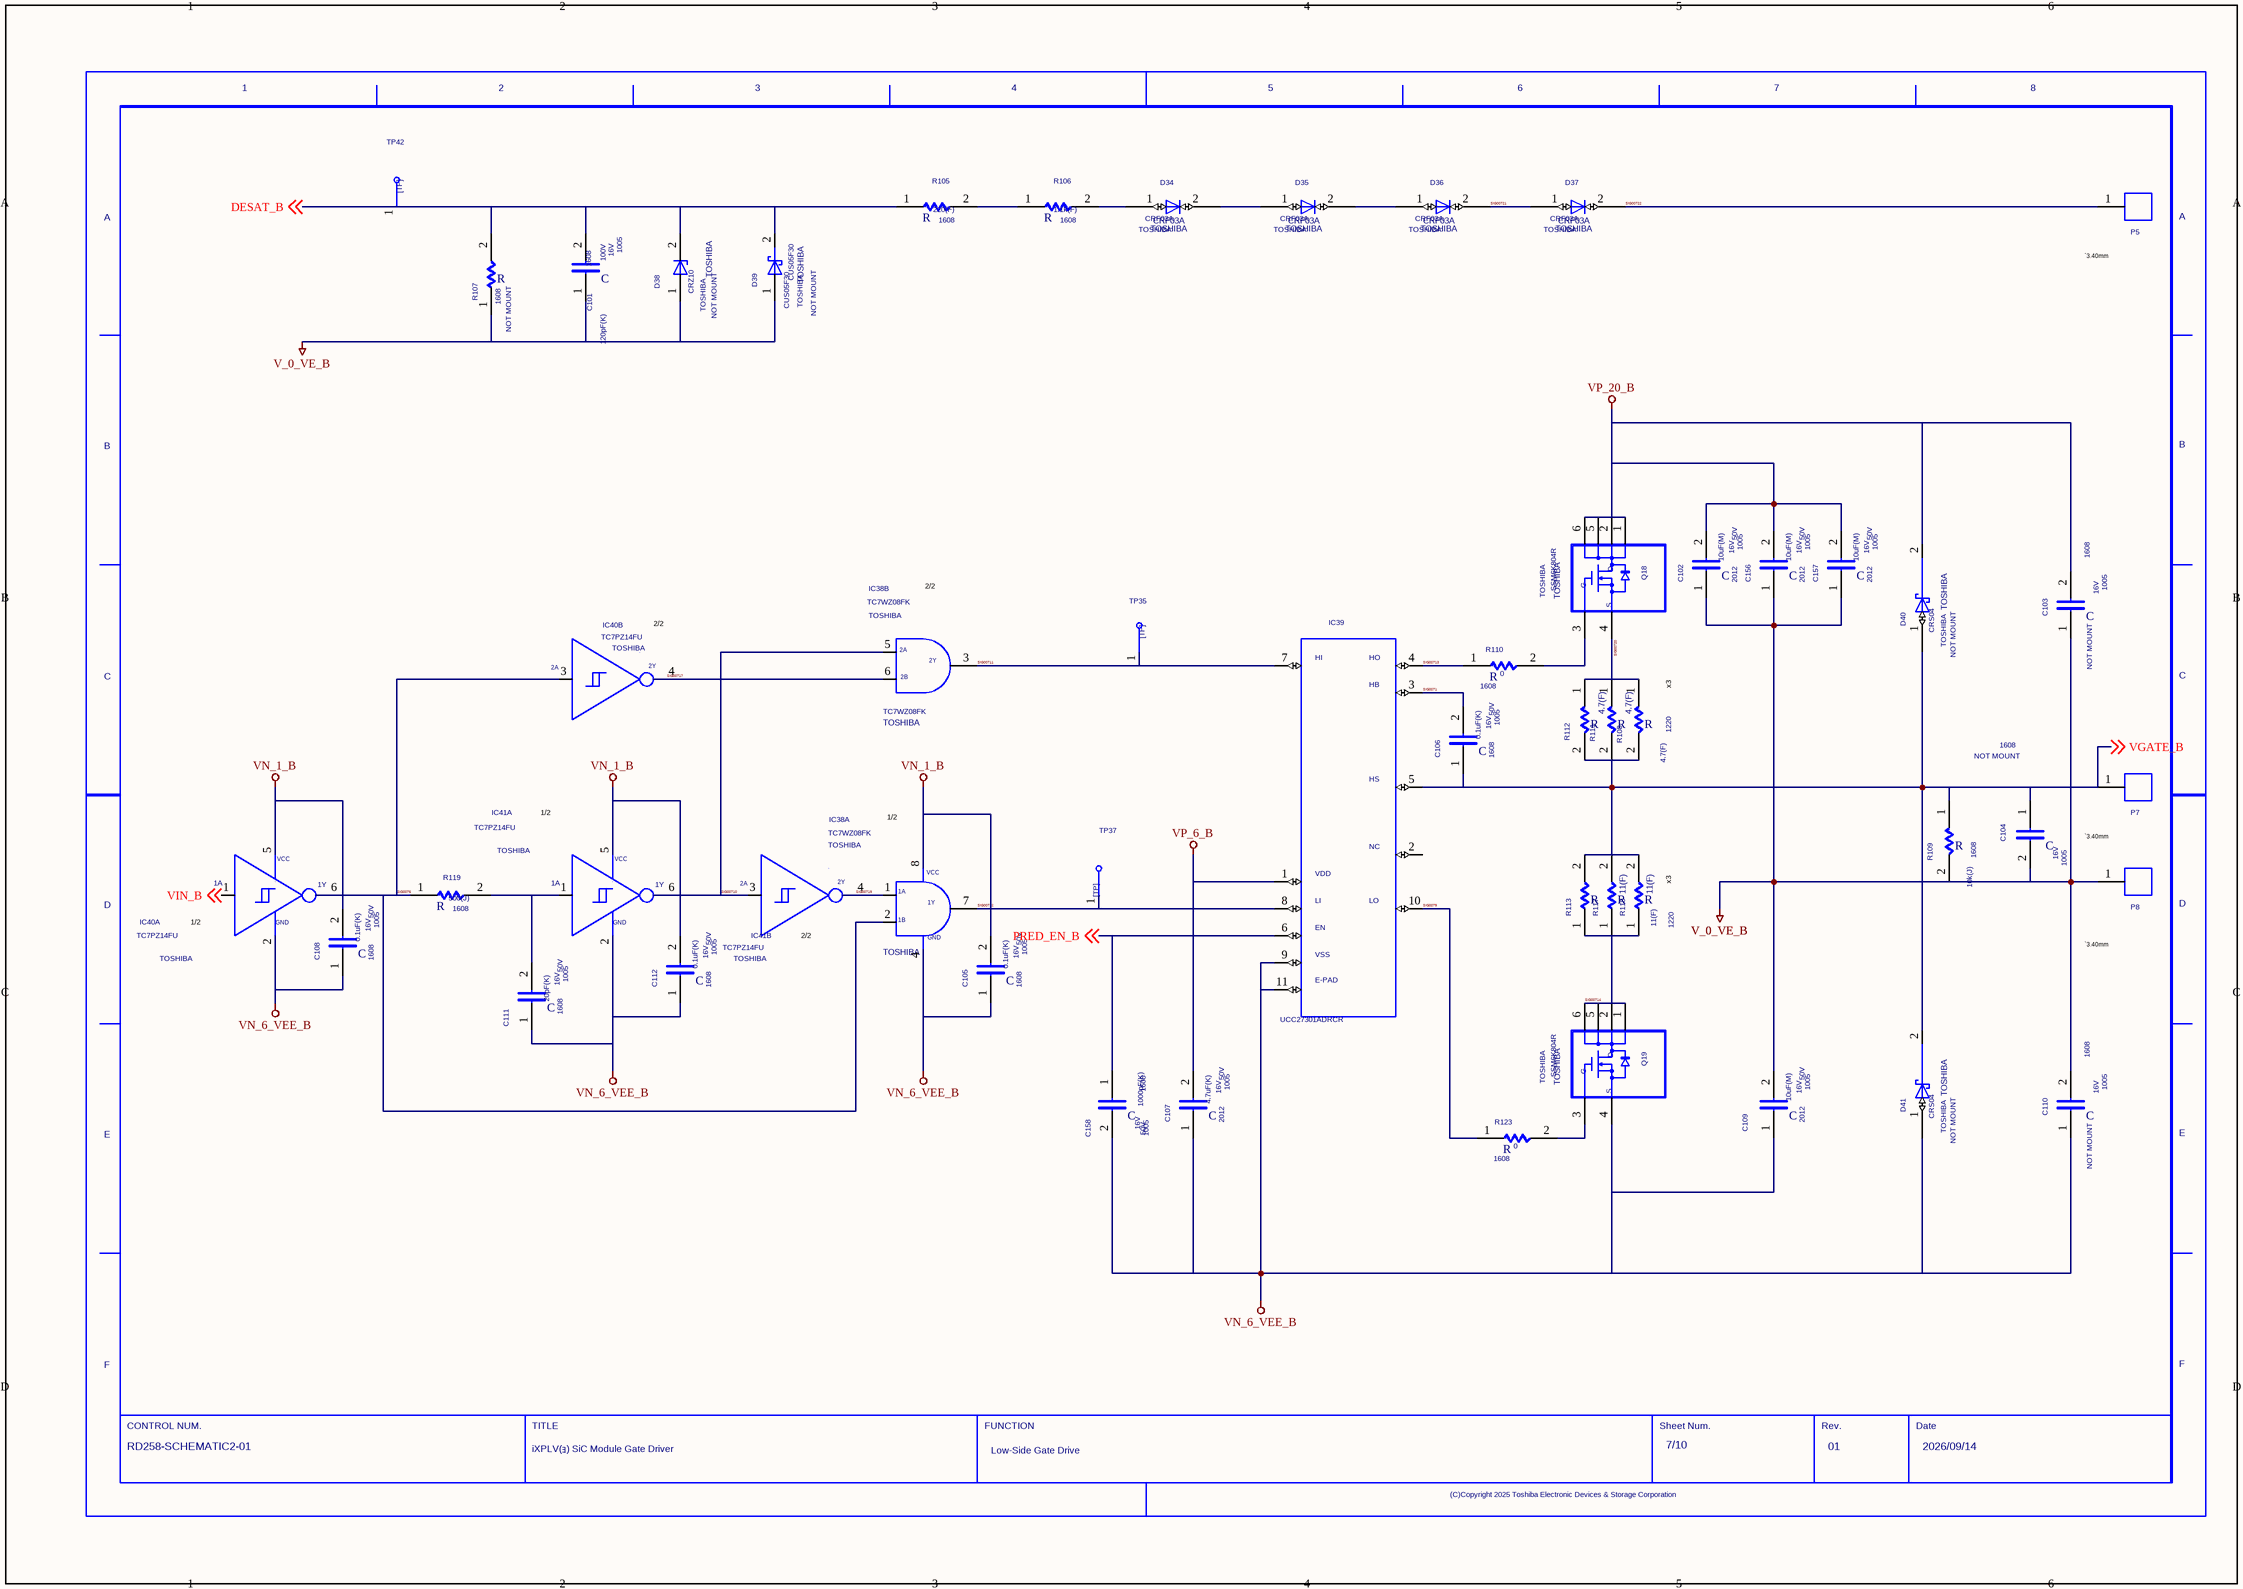
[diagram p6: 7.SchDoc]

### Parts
(Parts that share a designator on the sheet are numbered #1, #2 ... from top to bottom, then left to right.)
C101  VAL1: 120pF(K)  CODE: 1005  VOLTAGE: 16V  SIZECODESMD: 1608  VAL2: 100V  (hidden comment: C)
C102  VAL1: 10uF(M)  CODE: 1005  VOLTAGE: 16V  SIZECODESMD: 2012  VAL2: 50V  (hidden comment: C)
C103  CODE: 1005  VOLTAGE: 16V  NOTMOUNT: NOT MOUNT  SIZECODESMD: 1608  (hidden comment: C)
C104  CODE: 1005  VOLTAGE: 16V  NOTMOUNT: NOT MOUNT  SIZECODESMD: 1608  (hidden comment: C)
C105  VAL1: 0.1uF(K)  CODE: 1005  VOLTAGE: 16V  SIZECODESMD: 1608  VAL2: 50V  (hidden comment: C)
C106  VAL1: 0.1uF(K)  CODE: 1005  VOLTAGE: 16V  SIZECODESMD: 1608  VAL2: 50V  (hidden comment: C)
C107  VAL1: 4.7uF(K)  CODE: 1005  VOLTAGE: 16V  SIZECODESMD: 2012  VAL2: 50V  (hidden comment: C)
C108  VAL1: 0.1uF(K)  CODE: 1005  VOLTAGE: 16V  SIZECODESMD: 1608  VAL2: 50V  (hidden comment: C)
C109  VAL1: 10uF(M)  CODE: 1005  VOLTAGE: 16V  SIZECODESMD: 2012  VAL2: 50V  (hidden comment: C)
C110  CODE: 1005  VOLTAGE: 16V  NOTMOUNT: NOT MOUNT  SIZECODESMD: 1608  (hidden comment: C)
C111  VAL1: 20pF(K)  CODE: 1005  VOLTAGE: 16V  SIZECODESMD: 1608  VAL2: 50V  (hidden comment: C)
C112  VAL1: 0.1uF(K)  CODE: 1005  VOLTAGE: 16V  SIZECODESMD: 1608  VAL2: 50V  (hidden comment: C)
C156  VAL1: 10uF(M)  CODE: 1005  VOLTAGE: 16V  SIZECODESMD: 2012  VAL2: 50V  (hidden comment: C)
C157  VAL1: 10uF(M)  CODE: 1005  VOLTAGE: 16V  SIZECODESMD: 2012  VAL2: 50V  (hidden comment: C)
C158  VAL1: 1000pF(K)  CODE: 1005  VOLTAGE: 16V  SIZECODESMD: 1608  VAL2: 50V  (hidden comment: C)
D34  VENDOR: TOSHIBA  (hidden comment: CRF03A)
D35  VENDOR: TOSHIBA  (hidden comment: CRF03A)
D36  VENDOR: TOSHIBA  (hidden comment: CRF03A)
D37  VENDOR: TOSHIBA  (hidden comment: CRF03A)
D38  VENDOR: TOSHIBA  NOTMOUNT: NOT MOUNT  (hidden comment: CRZ10)
D39  VENDOR: TOSHIBA  NOTMOUNT: NOT MOUNT  (hidden comment: CUS05F30)
D40  VENDOR: TOSHIBA  NOTMOUNT: NOT MOUNT  (hidden comment: CRS04)
D41  VENDOR: TOSHIBA  NOTMOUNT: NOT MOUNT  (hidden comment: CRS04)
IC38  VENDOR: TOSHIBA  (hidden comment: TC7WZ08FK)  (parts A,B of 2)
IC39  VAL3: UCC27301ADRCR  (hidden comment: UCC27301A)
IC40  USERCOMPTEXT3: TOSHIBA  VAL3: TC7PZ14FU  (hidden comment: TC7PZ17FU)  (parts A,B of 2)
IC41  USERCOMPTEXT3: TOSHIBA  VAL3: TC7PZ14FU  (hidden comment: TC7PZ17FU)  (parts A,B of 2)
P5  TH  (value not drawn)
P7  TH  (value not drawn)
P8  TH  (value not drawn)
Q18  VENDOR: TOSHIBA  (hidden comment: SSM6K804R)
Q19  VENDOR: TOSHIBA  (hidden comment: SSM6K804R)
R105  VAL1: 220(F)  SIZECODESMD: 1608  (hidden comment: R)
R106  VAL1: 1.1k(F)  SIZECODESMD: 1608  (hidden comment: R)
R107  NOTMOUNT: NOT MOUNT  SIZECODESMD: 1608  (hidden comment: R)
R108  VAL1: 4.7(F)  (hidden comment: R)
R109  VAL1: 10k(J)  SIZECODESMD: 1608  (hidden comment: R)
R110  VAL1: 0  SIZECODESMD: 1608  (hidden comment: R)
R111  VAL1: 4.7(F)  (hidden comment: R)
R112  VAL1: 4.7(F)  SIZECODESMD: 1220  (hidden comment: R)
R113  VAL1: 11(F)  SIZECODESMD: 1220  (hidden comment: R)
R117  VAL1: 11(F)  (hidden comment: R)
R118  VAL1: 11(F)  (hidden comment: R)
R119  VAL1: 500(J)  SIZECODESMD: 1608  (hidden comment: R)
R123  VAL1: 0  SIZECODESMD: 1608  (hidden comment: R)
TP35  TP  (value not drawn)
TP37  TP  (value not drawn)
TP42  TP  (value not drawn)
U?#7  DATE: 2026/09/14  DRAWINGNUMBER: RD258-SCHEMATIC2-01  TITLE: iXPLV(ｮ) SiC Module Gate Driver  FUNCTION: Low-Side Gate Drive  SHEETNUMBER: 7/10  REVISION: 01  (hidden comment: WAKU_DEF100)

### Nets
V_0_VE_B: C101.1 C102.1 C103.1 C104.2 C109.2 C110.2 C156.1 C157.1 D38.1(A) D39.1(A) P8.1 R107.1 R109.2
VN_1_B: C105.2 C108.2 C112.2 IC38.8 IC40.5 IC41.5
VN_6_VEE_B: C105.1 C107.1 C108.1 C109.1 C110.1 C111.1 C112.1 C158.2 D41.1(A) IC38.4 IC39.9 IC39.11 IC40.2 IC41.2 Q19.4
VP_6_B: C107.2 IC39.1
VP_20_B: C102.2 C103.2 C156.2 C157.2 D40.2(C) Q18.1 Q18.2 Q18.5 Q18.6
DESAT_B: C101.2 D38.2(C) D39.2(C) R105.1 R107.2 TP42.1 ; off-sheet DESAT_B
PRED_EN_B: C158.1 IC39.6 ; off-sheet PRED_EN_B
SIG0071: C106.2 IC39.3
SIG0072: D34.2(C) D35.1(A)
SIG0073: D34.1(A) R106.2
SIG0075: Q18.3 R110.2
SIG0076: IC38.2 IC40.3 IC40.6 R119.1
SIG0077: D35.2(C) D36.1(A)
SIG0078: R105.2 R106.1
SIG0079: IC39.10 R123.1
SIG00710: IC38.5 IC41.3 IC41.6
SIG00711: IC38.3 IC39.7 TP35.1
SIG00712: IC38.7 IC39.8 TP37.1
SIG00713: IC39.4 R110.1
SIG00714: Q19.1 Q19.2 Q19.5 Q19.6 R113.1 R117.1 R118.1
SIG00716: C111.2 IC41.1 R119.2
SIG00717: IC38.6 IC40.4
SIG00718: Q19.3 R123.2
SIG00719: IC38.1 IC41.4
SIG00720: Q18.4 R108.1 R111.1 R112.1
SIG00721: D36.2(C) D37.1(A)
SIG00722: D37.2(C) P5.1
VGATE_B: C104.1 C106.1 D40.1(A) D41.2(C) IC39.5 P7.1 R108.2 R109.1 R111.2 R112.2 R113.2 R117.2 R118.2 ; off-sheet VGATE_B
VIN_B: IC40.1 ; off-sheet VIN_B

Not connected (* = marked no-connect by the designer): IC39 2

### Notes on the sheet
- (near P5) `3.40mm
  TH
- 2/2
- (near IC40) 2/2
- (near R108) x3
- (near IC41) 1/2
- (near IC38) 1/2
- `3.40mm
  TH
- (near IC40) 1/2
- (near IC41) 2/2
- (near R118) x3

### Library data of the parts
C101 C102 C105-C109 C111 C112 C156-C158 = C: as C24 on sheet 1
C103 C104 C110 = C: as C91 on sheet 2
D34-D37 = CRF03A: as D26 on sheet 2
D38 = CRZ10: as D30 on sheet 2
D39 = CUS05F30: as D31 on sheet 2
D40 D41 = CRS04: as D32 on sheet 2
IC38 = TC7WZ08FK_1: as IC34 on sheet 2
IC39 = UCC27301A: as IC35 on sheet 2
IC40 IC41 = TC7PZ14FU_2: TIME: 11:55:01; UPDATEUSER: t5459927; UPDATETIME: 19:09:34; SAVECOUNT: 4; SPLIT_INST: TRUE; PSPICETEMPLATE: X^@REFDES %1A %GND %2A %2Y %VCC %1Y @MODEL; SWAP_INFO: (S1+S2); OriginalSymbolOrigin: (5080,15240); CaptureCellPackProp: TC7PZ14FU_2A; FUNCN: TC7PZ14FU_1; INSTANCENAME: INS2255542
P5 P7 = TH: as P3 on sheet 2
P8 = TH: as P4 on sheet 2
Q18 Q19 = SSM6K804R: as Q15 on sheet 2
R105 R106 R119 = R: as R187 on sheet 1
R107 = R: as R87 on sheet 2
R108 R111 R117 R118 = R: as R91 on sheet 2
R109 = R: as R89 on sheet 2
R110 R123 = R: as R90 on sheet 2
R112 R113 = R: as R88 on sheet 2
TP35 = TP: as TP30 on sheet 2
TP37 = TP: as TP32 on sheet 2
TP42 = TP: as TP41 on sheet 2
U?#7 = WAKU_DEF100: PLOTTIME: HH:MM; SAVEAREA0: -63393,-16950,474261,314592; TIME: 14:30:25; UPDATEUSER: t5459927; UPDATETIME: 14:59:41; SAVECOUNT: 4; OriginalSymbolOrigin: (10160,284480); SHTSAVECOUNT: 36

## Sheet 8.SchDoc
size 420 x 297 mm
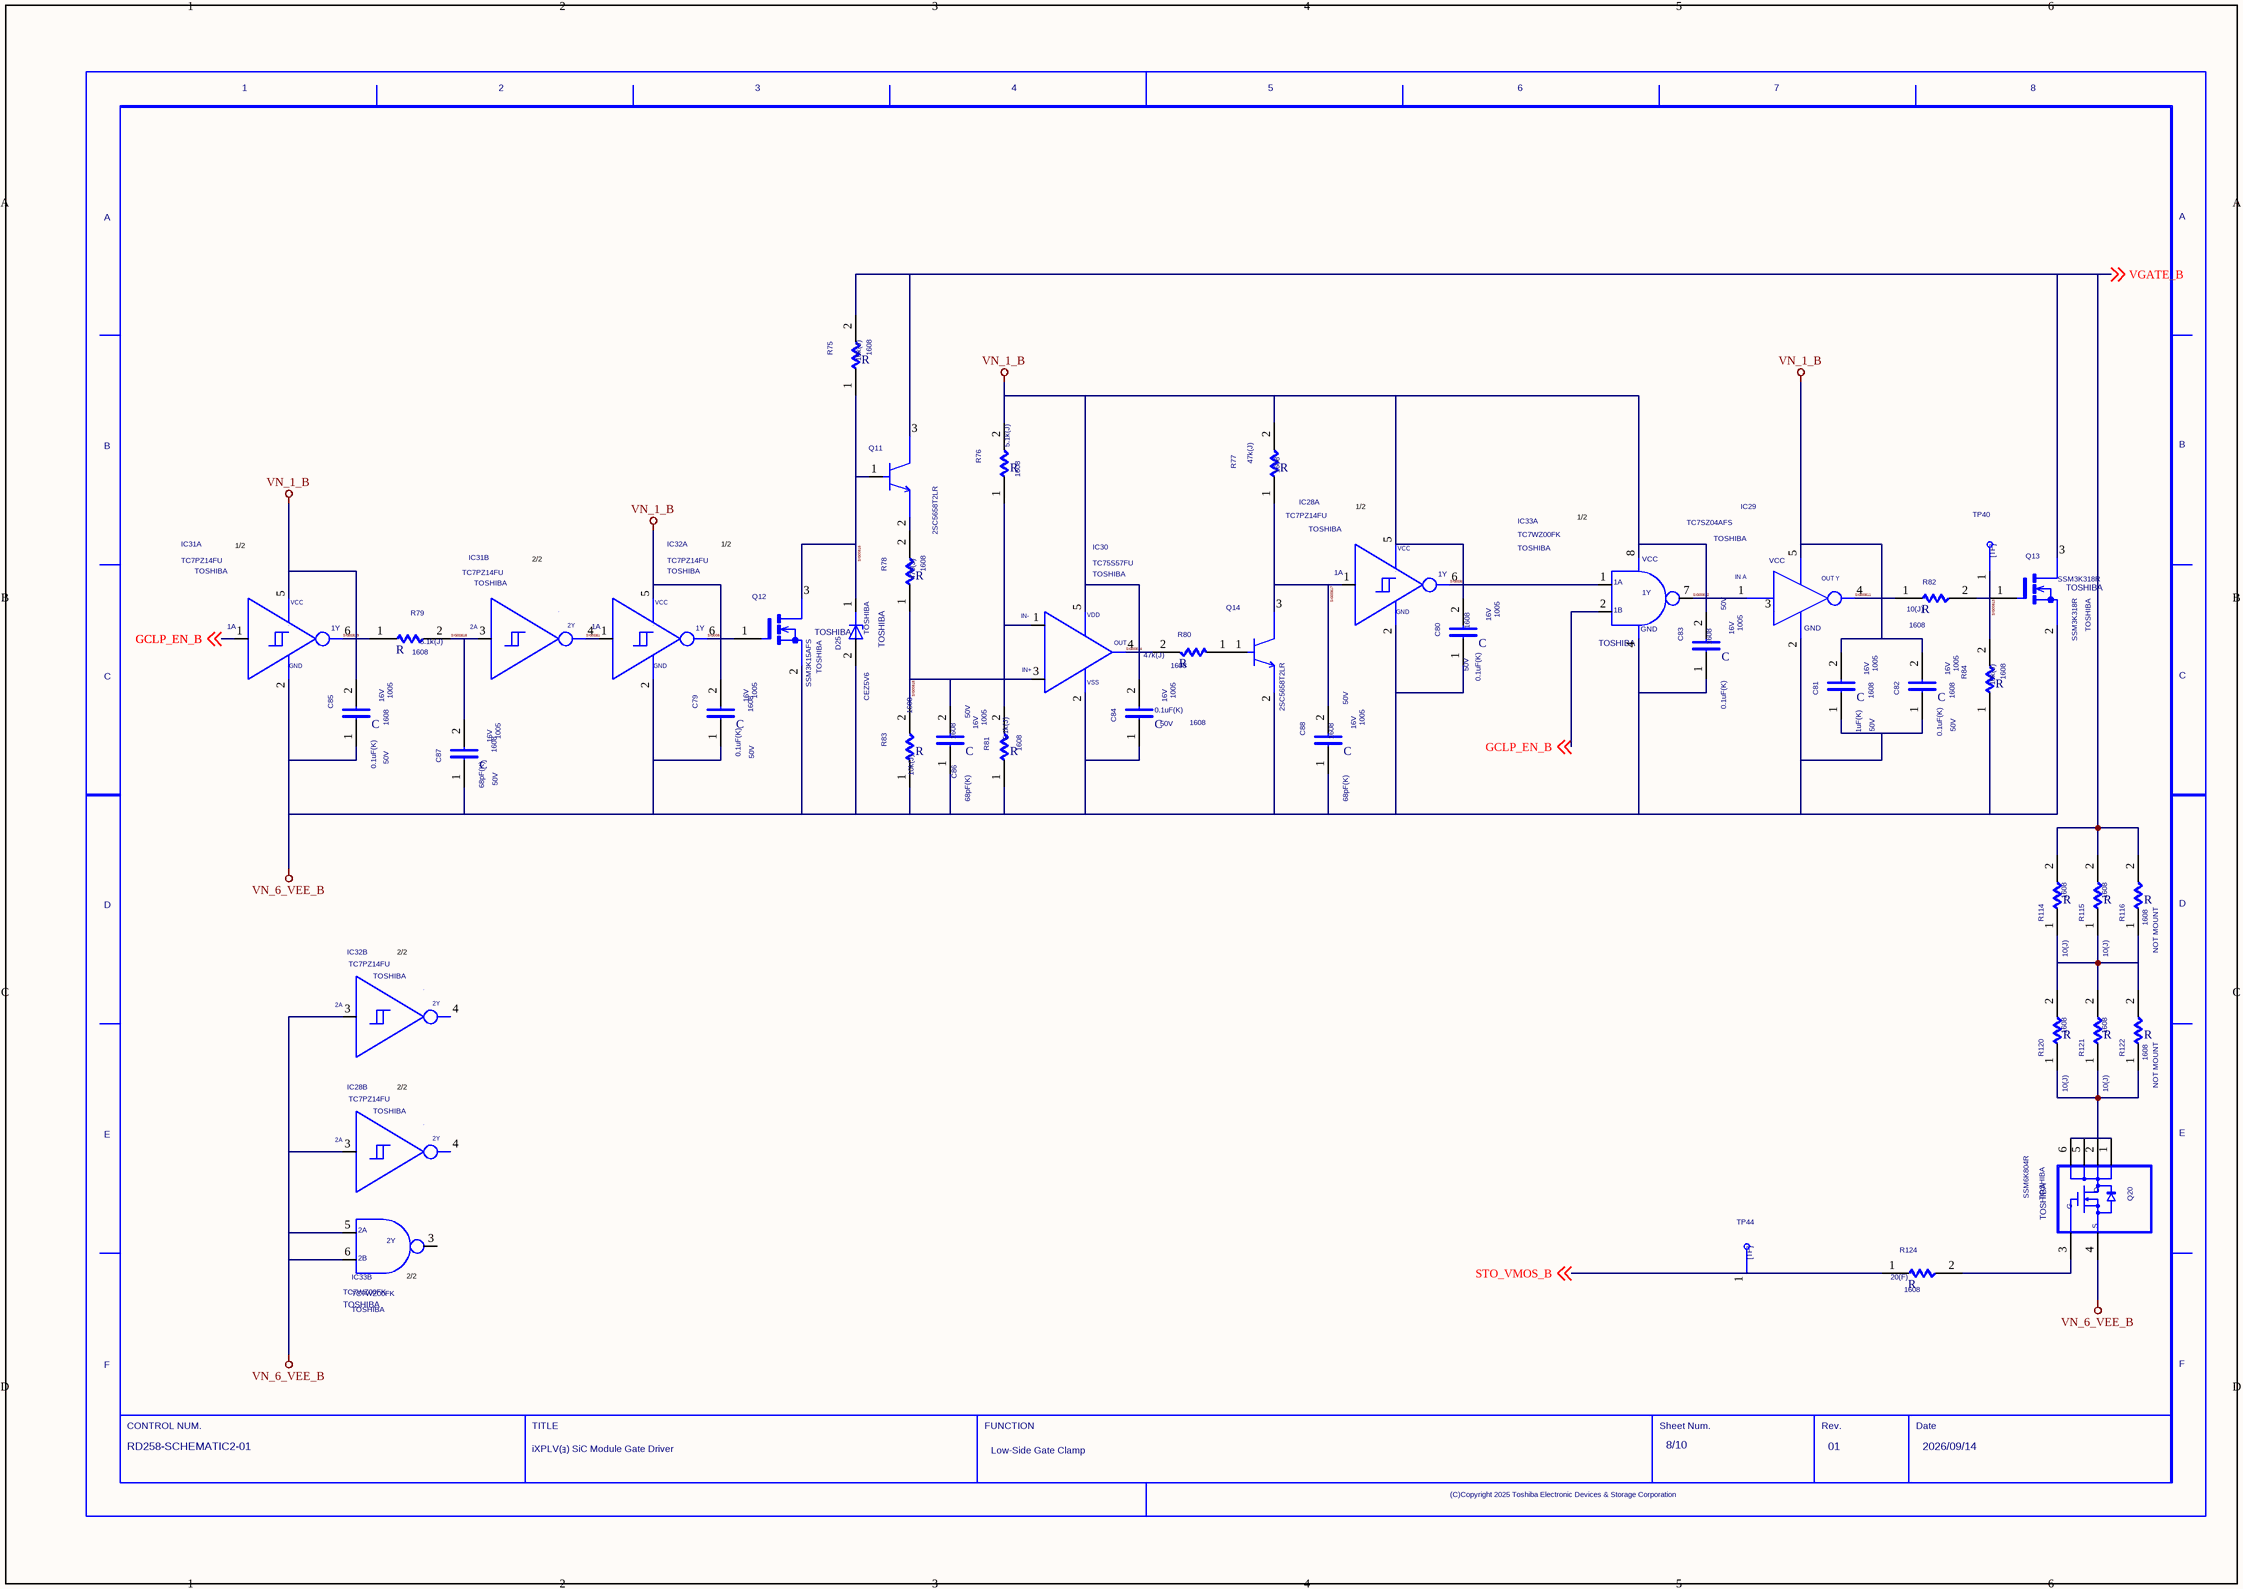
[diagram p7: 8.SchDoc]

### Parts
(Parts that share a designator on the sheet are numbered #1, #2 ... from top to bottom, then left to right.)
C79  VAL1: 0.1uF(K)  CODE: 1005  VOLTAGE: 16V  SIZECODESMD: 1608  VAL2: 50V  (hidden comment: C)
C80  VAL1: 0.1uF(K)  CODE: 1005  VOLTAGE: 16V  SIZECODESMD: 1608  VAL2: 50V  (hidden comment: C)
C81  VAL1: 1uF(K)  CODE: 1005  VOLTAGE: 16V  SIZECODESMD: 1608  VAL2: 50V  (hidden comment: C)
C82  VAL1: 0.1uF(K)  CODE: 1005  VOLTAGE: 16V  SIZECODESMD: 1608  VAL2: 50V  (hidden comment: C)
C83  VAL1: 0.1uF(K)  CODE: 1005  VOLTAGE: 16V  SIZECODESMD: 1608  VAL2: 50V  (hidden comment: C)
C84  VAL1: 0.1uF(K)  CODE: 1005  VOLTAGE: 16V  SIZECODESMD: 1608  VAL2: 50V  (hidden comment: C)
C85  VAL1: 0.1uF(K)  CODE: 1005  VOLTAGE: 16V  SIZECODESMD: 1608  VAL2: 50V  (hidden comment: C)
C86  VAL1: 68pF(K)  CODE: 1005  VOLTAGE: 16V  SIZECODESMD: 1608  VAL2: 50V  (hidden comment: C)
C87  VAL1: 68pF(K)  CODE: 1005  VOLTAGE: 16V  SIZECODESMD: 1608  VAL2: 50V  (hidden comment: C)
C88  VAL1: 68pF(K)  CODE: 1005  VOLTAGE: 16V  SIZECODESMD: 1608  VAL2: 50V  (hidden comment: C)
D25  VENDOR: TOSHIBA  (hidden comment: CEZ5V6)
IC28  USERCOMPTEXT3: TOSHIBA  VAL3: TC7PZ14FU  (hidden comment: TC7PZ17FU)  (parts A,B of 2)
IC29  USERCOMPTEXT3: TOSHIBA  (hidden comment: TC7SZ04AFS)
IC30  USERCOMPTEXT3: TOSHIBA  (hidden comment: TC75S57FU)
IC31  USERCOMPTEXT3: TOSHIBA  VAL3: TC7PZ14FU  (hidden comment: TC7PZ17FU)  (parts A,B of 2)
IC32  USERCOMPTEXT3: TOSHIBA  VAL3: TC7PZ14FU  (hidden comment: TC7PZ17FU)  (parts A,B of 2)
IC33  VENDOR: TOSHIBA  (hidden comment: TC7WZ00FK)  (parts A,B of 2)
Q11  VAL3: 2SC5658T2LR  (hidden comment: 2SC5658J)
Q12  VENDOR: TOSHIBA  (hidden comment: SSM3K15AFS)
Q13  VENDOR: TOSHIBA  (hidden comment: SSM3K318R)
Q14  VAL3: 2SC5658T2LR  (hidden comment: 2SC5658J)
Q20  VENDOR: TOSHIBA  (hidden comment: SSM6K804R)
R75  VAL1: 10k(J)  SIZECODESMD: 1608  (hidden comment: R)
R76  VAL1: 5.1k(J)  SIZECODESMD: 1608  (hidden comment: R)
R77  VAL1: 47k(J)  SIZECODESMD: 1608  (hidden comment: R)
R78  VAL1: 470(J)  SIZECODESMD: 1608  (hidden comment: R)
R79  VAL1: 5.1k(J)  SIZECODESMD: 1608  (hidden comment: R)
R80  VAL1: 47k(J)  SIZECODESMD: 1608  (hidden comment: R)
R81  VAL1: 5.1k(J)  SIZECODESMD: 1608  (hidden comment: R)
R82  VAL1: 10(J)  SIZECODESMD: 1608  (hidden comment: R)
R83  VAL1: 10k(J)  SIZECODESMD: 1608  (hidden comment: R)
R84  VAL1: 10k(J)  SIZECODESMD: 1608  (hidden comment: R)
R114  VAL1: 10(J)  SIZECODESMD: 1608  (hidden comment: R)
R115  VAL1: 10(J)  SIZECODESMD: 1608  (hidden comment: R)
R116  NOTMOUNT: NOT MOUNT  SIZECODESMD: 1608  (hidden comment: R)
R120  VAL1: 10(J)  SIZECODESMD: 1608  (hidden comment: R)
R121  VAL1: 10(J)  SIZECODESMD: 1608  (hidden comment: R)
R122  NOTMOUNT: NOT MOUNT  SIZECODESMD: 1608  (hidden comment: R)
R124  VAL1: 20(F)  SIZECODESMD: 1608  (hidden comment: R)
TP40  TP  (value not drawn)
TP44  TP  (value not drawn)
U?#8  DATE: 2026/09/14  DRAWINGNUMBER: RD258-SCHEMATIC2-01  TITLE: iXPLV(ｮ) SiC Module Gate Driver  FUNCTION: Low-Side Gate Clamp  SHEETNUMBER: 8/10  REVISION: 01  (hidden comment: WAKU_DEF100)

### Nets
VN_1_B: C79.2 C80.2 C81.2 C82.2 C83.2 C84.2 C85.2 IC28.5 IC29.5 IC30.5 IC31.5 IC32.5 IC33.8 R76.2 R77.2
VN_6_VEE_B: C79.1 C80.1 C81.1 C82.1 C83.1 C84.1 C85.1 C86.1 C87.1 C88.1 D25.2(A) IC28.2 IC28.3 IC29.2 IC30.2 IC31.2 IC32.2 IC32.3 IC33.4 IC33.5(2A) IC33.6(2B) Q12.2(S) Q13.2(S) Q14.2(E) Q20.4 R81.1 R83.1 R84.1
GCLP_EN_B: IC31.1 IC33.2 ; off-sheet GCLP_EN_B
SIG0081: IC31.4 IC32.1
SIG0082: Q20.3 R124.2
SIG0083: R114.1 R115.1 R116.1 R120.2 R121.2 R122.2
SIG0084: IC32.6 Q12.1(G)
SIG0085: IC28.6 IC33.1
SIG0086: IC30.1 R76.1 R81.2
SIG0089: Q11.2(E) R78.2
SIG00810: Q20.1 Q20.2 Q20.5 Q20.6 R120.1 R121.1 R122.1
SIG00811: IC29.4 R82.1
SIG00812: IC29.1 IC33.7
SIG00813: Q13.1(G) R82.2 R84.2 TP40.1
SIG00814: IC30.4 R80.2
SIG00815: C86.2 IC30.3 R78.1 R83.2
SIG00816: D25.1(C) Q11.1(B) Q12.3(D) R75.1
SIG00817: C88.2 IC28.1 Q14.3(C) R77.1
SIG00818: C87.2 IC31.3 R79.2
SIG00819: IC31.6 R79.1
STO_VMOS_B: R124.1 TP44.1 ; off-sheet STO_VMOS_B
VGATE_B: Q11.3(C) Q13.3(D) R75.2 R114.2 R115.2 R116.2 ; off-sheet VGATE_B
NetQ14_1: Q14.1(B) R80.1

Not connected (* = marked no-connect by the designer): IC28 4; IC29 3; IC32 4; IC33 3(2Y)

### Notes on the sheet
- (near IC28) 1/2
- (near IC33) 1/2
- (near IC31) 1/2
- 2/2
- 1/2
- (near IC33) 2/2

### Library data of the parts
C79-C88 = C: as C24 on sheet 1
D25 = CEZ5V6: as D24 on sheet 3
IC28 IC31 IC32 = TC7PZ14FU_2: as IC23 on sheet 3
IC29 = TC7SZ04AFS: as IC22 on sheet 3
IC30 = TC75S57FU: TIME: 08:48:15; UPDATEUSER: t5459927; UPDATETIME: 11:03:38; SAVECOUNT: 3; PSPICETEMPLATE: X^@REFDES %INN %VSS %INP %OUT %VDD @MODEL; OriginalSymbolOrigin: (2540,0); INSTANCENAME: INS2262824
IC33 = TC7WZ00FK_1: as IC27 on sheet 3
Q11 = 2SC5658J: as Q7 on sheet 3
Q12 = SSM3K15AFS: as Q8 on sheet 3
Q13 = SSM3K318R: as Q9 on sheet 3
Q14 = 2SC5658J: as Q10 on sheet 3
Q20 = SSM6K804R: as Q17 on sheet 3
R75-R81 R83 R84 R114 R115 R120 R121 R124 = R: as R187 on sheet 1
R82 = R: as R72 on sheet 3
R116 R122 = R: as R87 on sheet 2
TP40 = TP: as TP39 on sheet 3
TP44 = TP: as TP43 on sheet 3
U?#8 = WAKU_DEF100: PLOTTIME: HH:MM; SAVEAREA0: -63393,-16950,474261,314592; TIME: 14:30:25; UPDATEUSER: t5459927; UPDATETIME: 14:29:35; SAVECOUNT: 4; OriginalSymbolOrigin: (10160,284480); SHTSAVECOUNT: 24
